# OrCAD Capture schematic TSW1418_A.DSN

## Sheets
1 BLOCK DIAGRAM: title: SCH, TSW1418EVM; rev: A; note: DC069
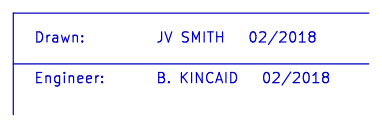
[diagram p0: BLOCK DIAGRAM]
2 LEDS, SWITCH & CLK SMAS: size B
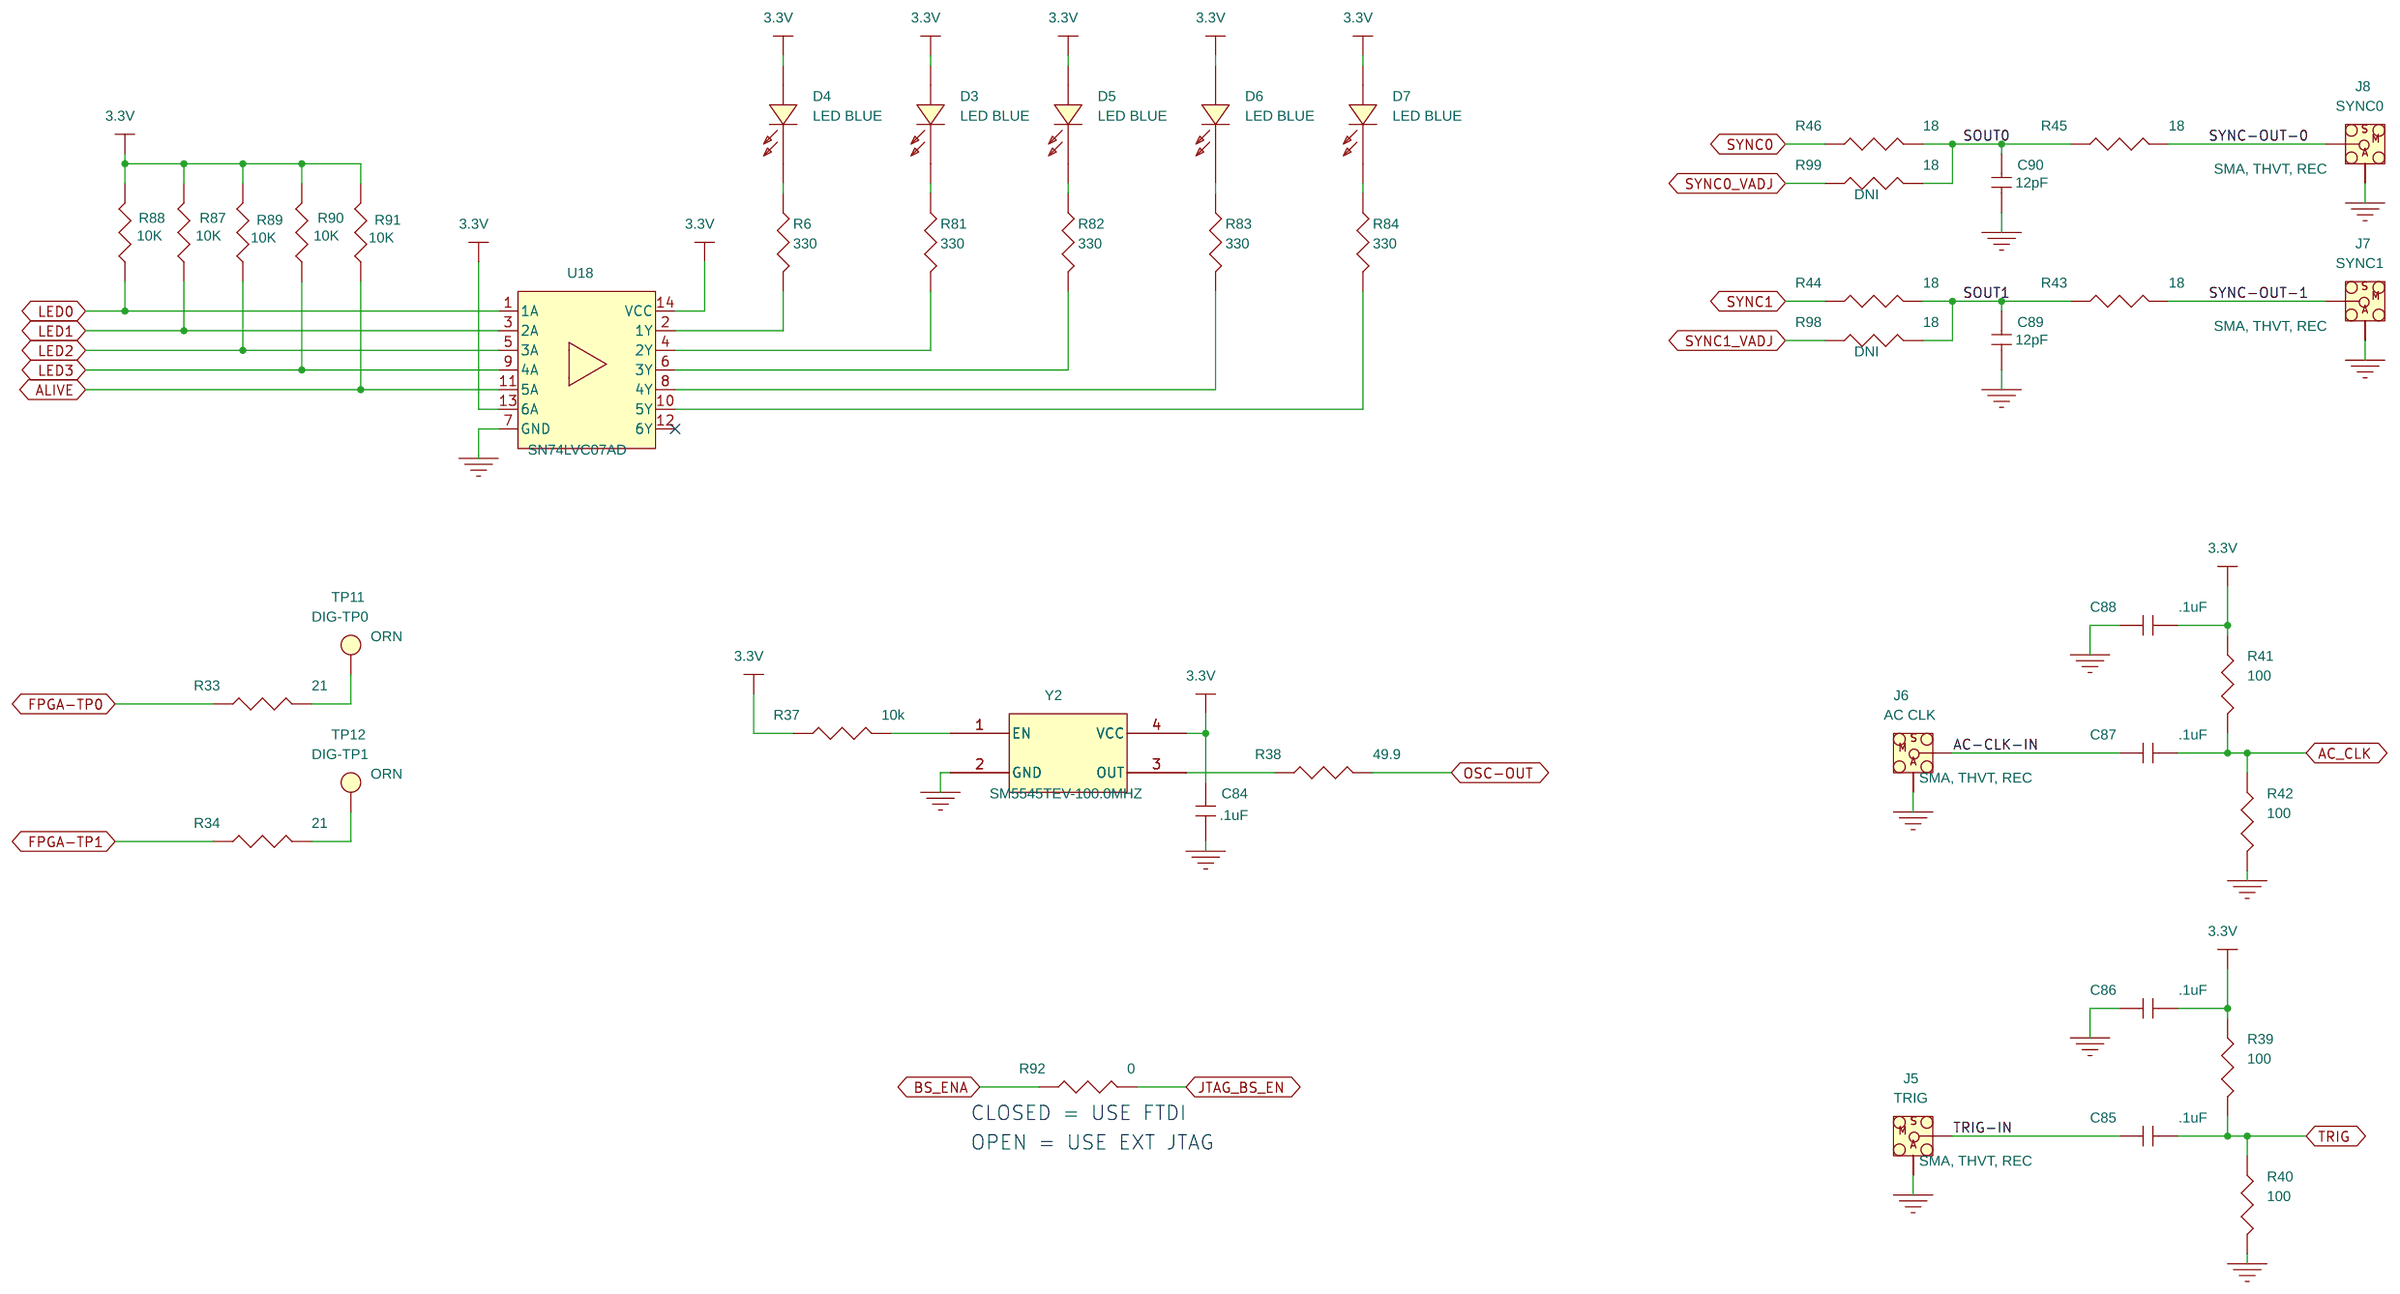
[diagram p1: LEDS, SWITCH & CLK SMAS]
3 ADC Interface, CMOS Header: size B
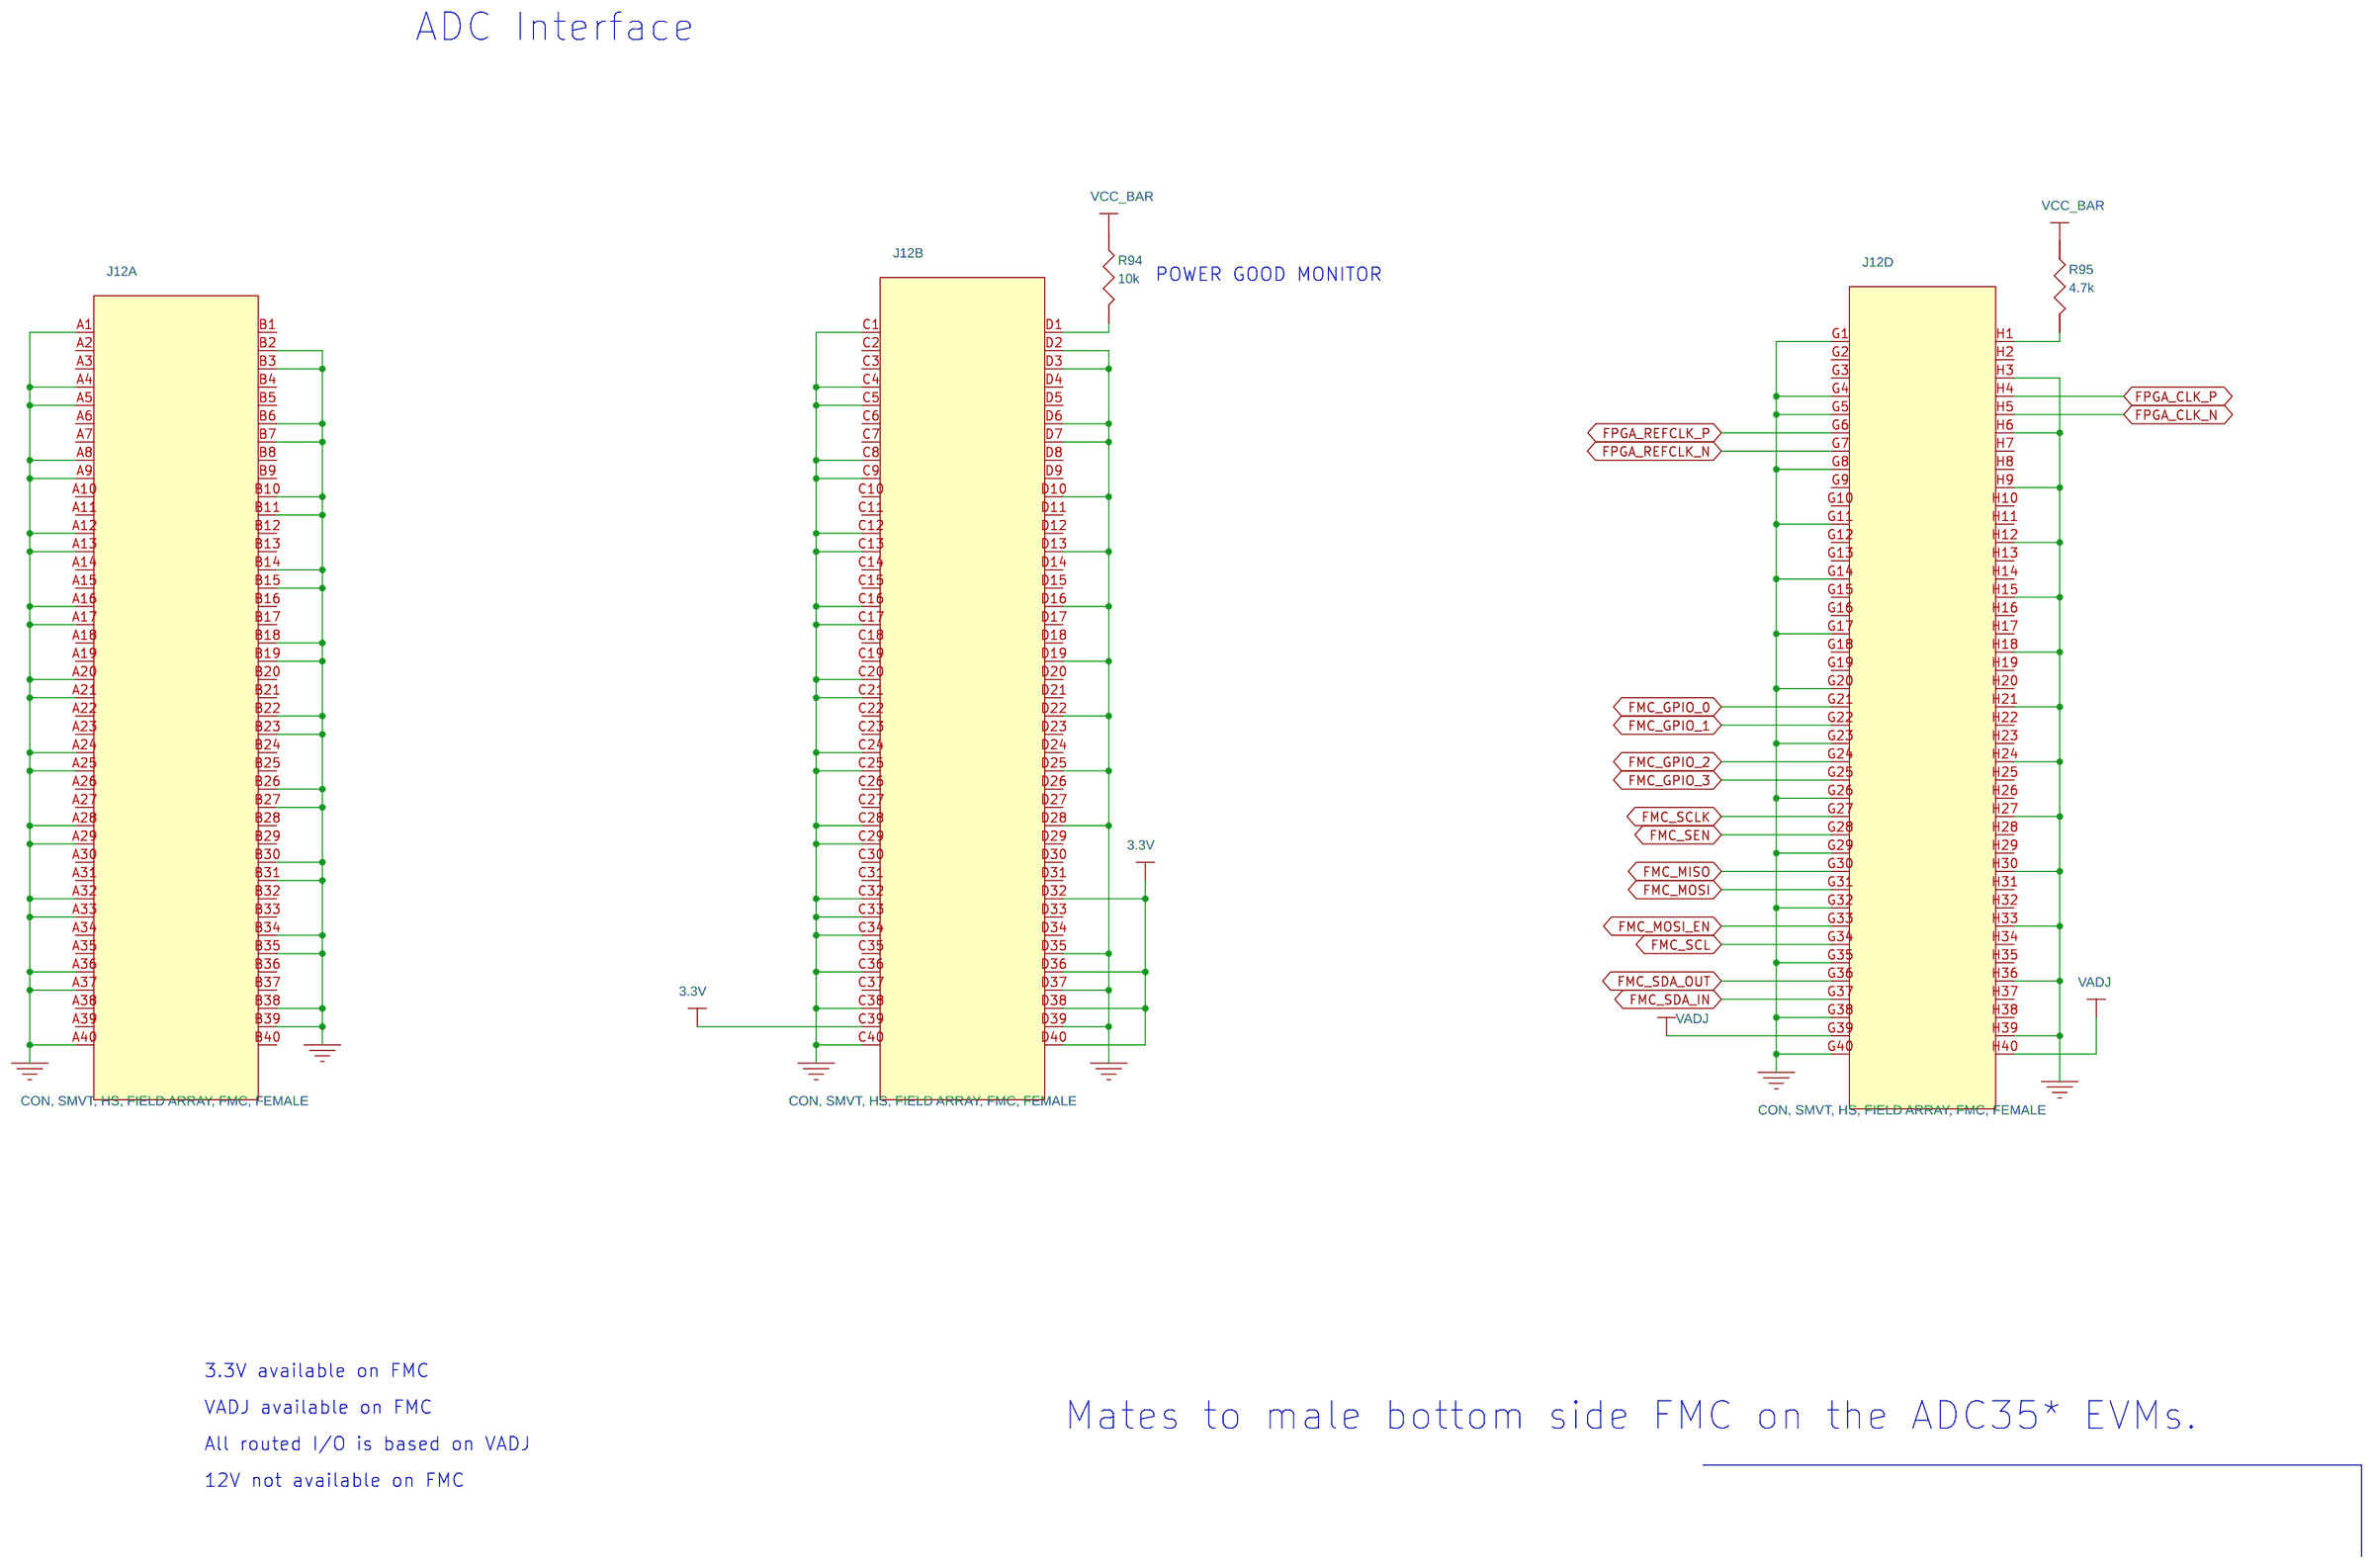
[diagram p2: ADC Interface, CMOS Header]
4 ADC I/F, FMC: size B
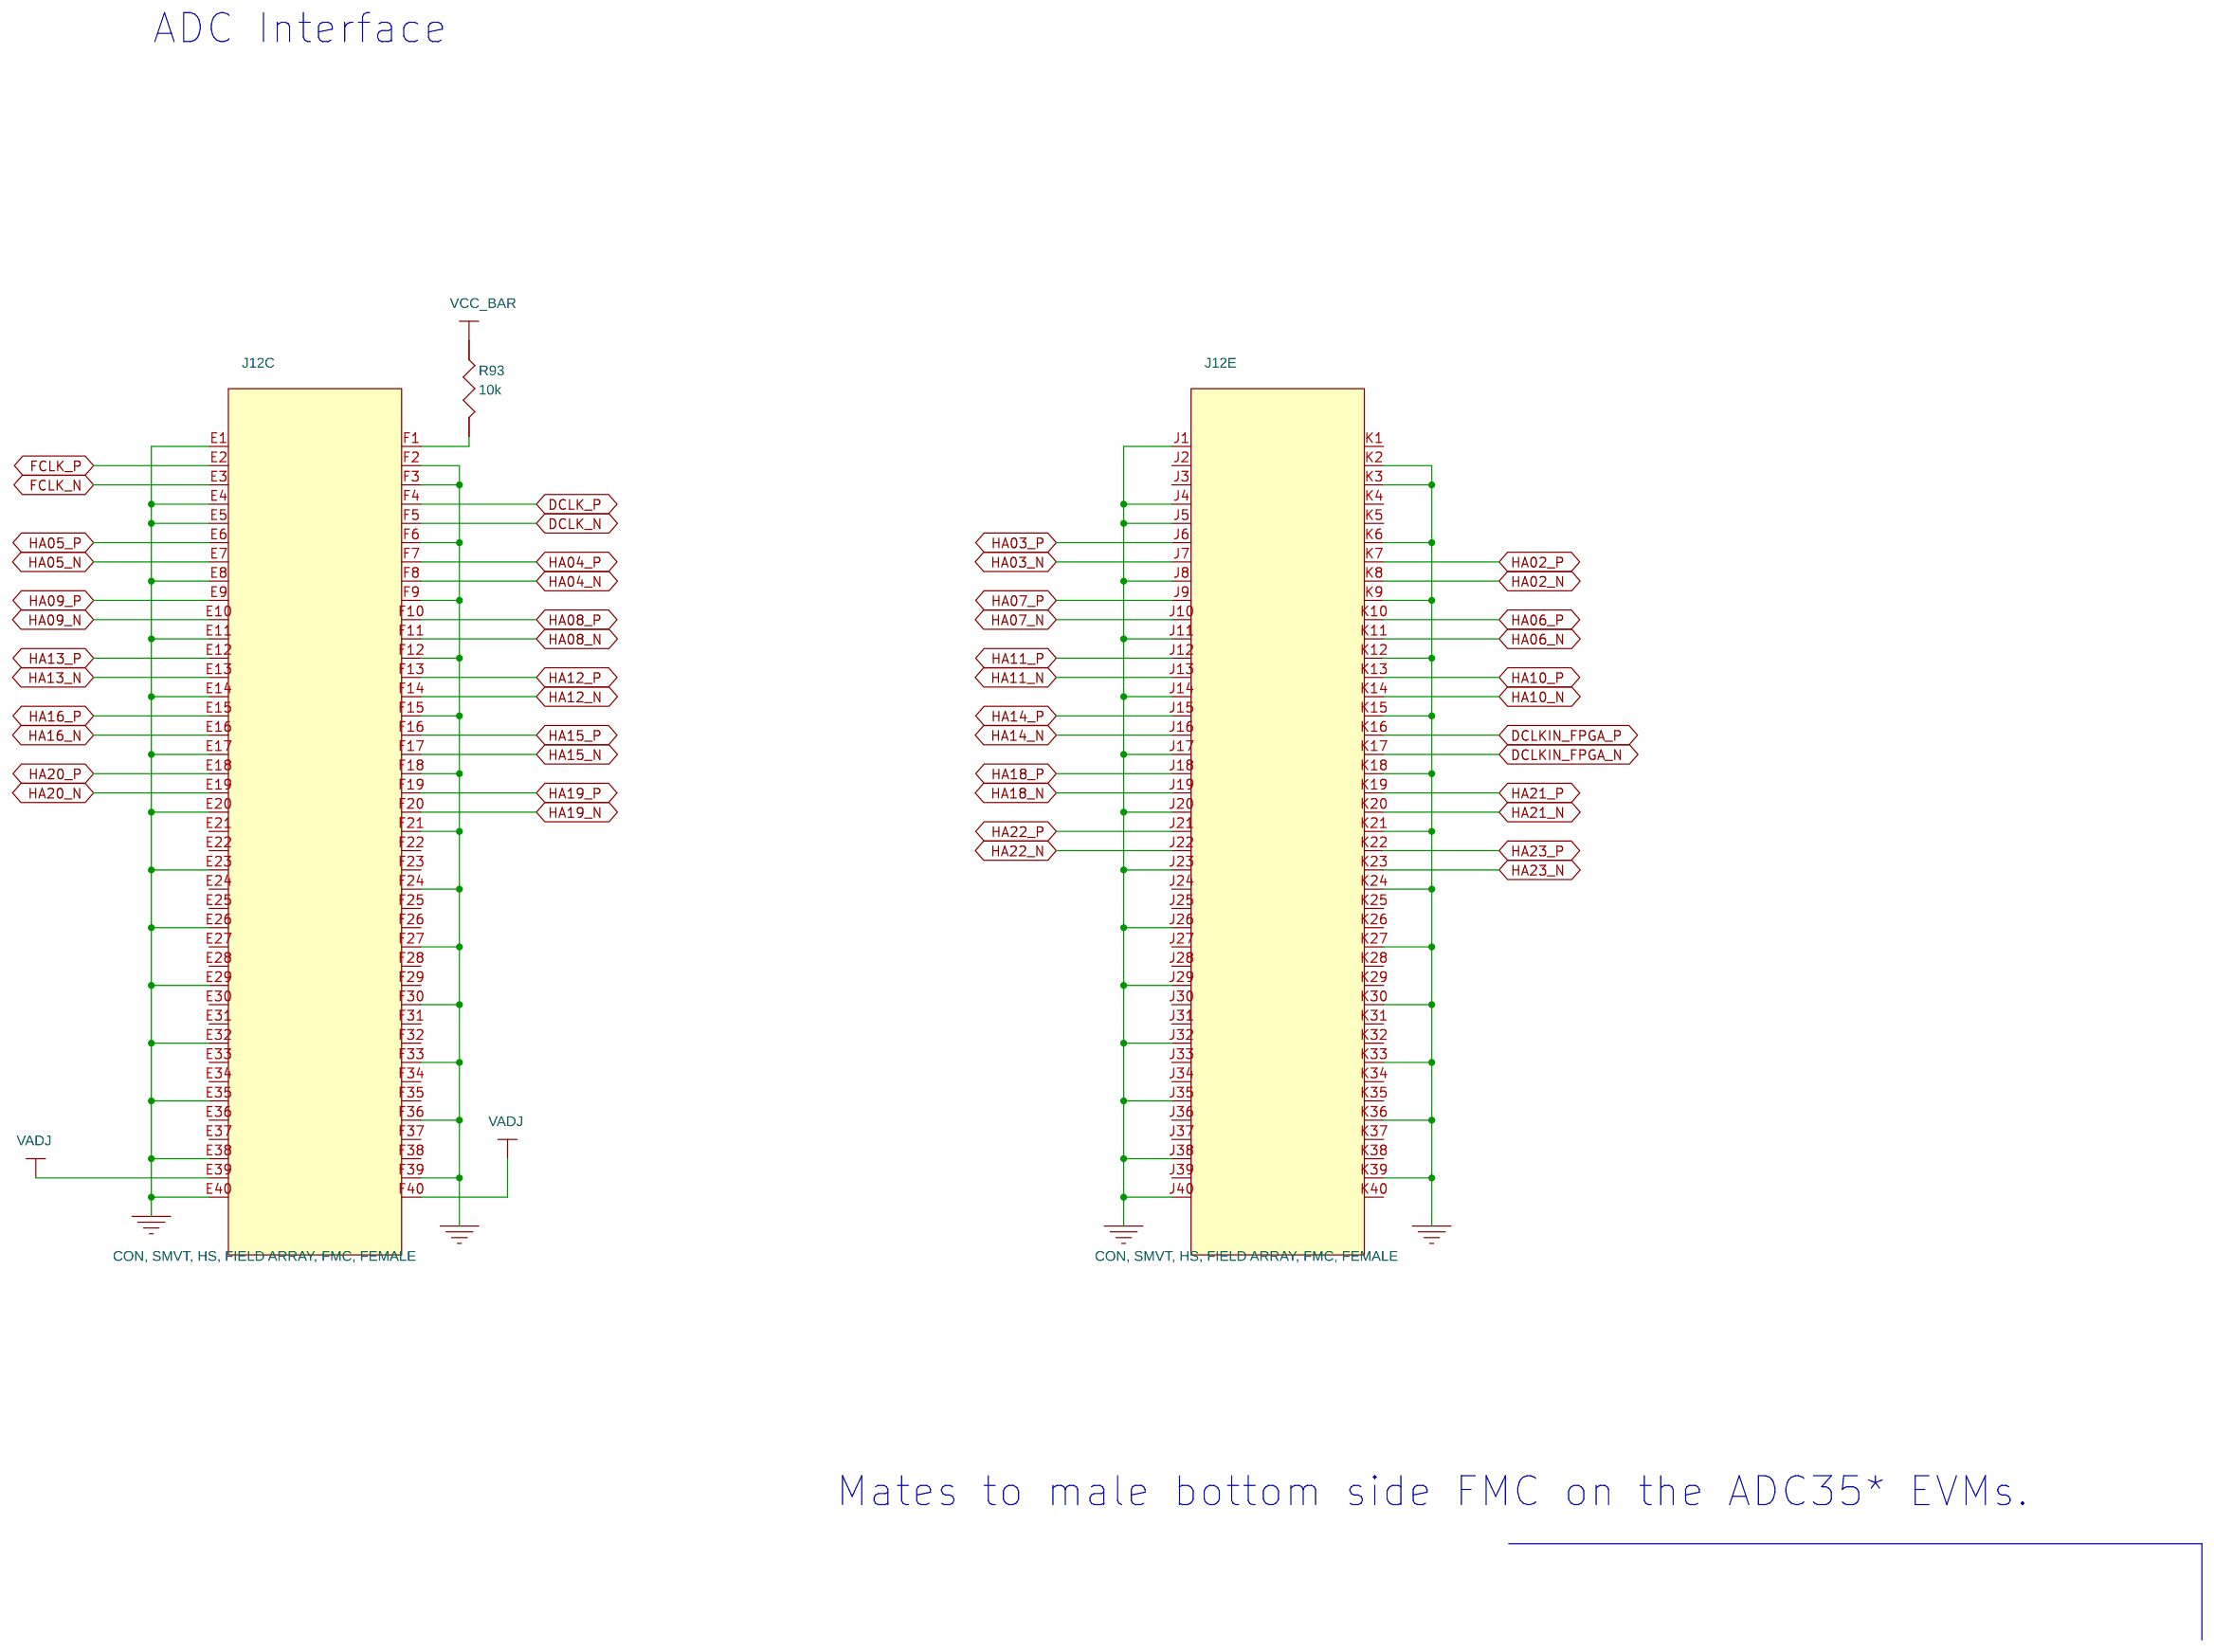
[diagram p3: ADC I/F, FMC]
5 USB: size B
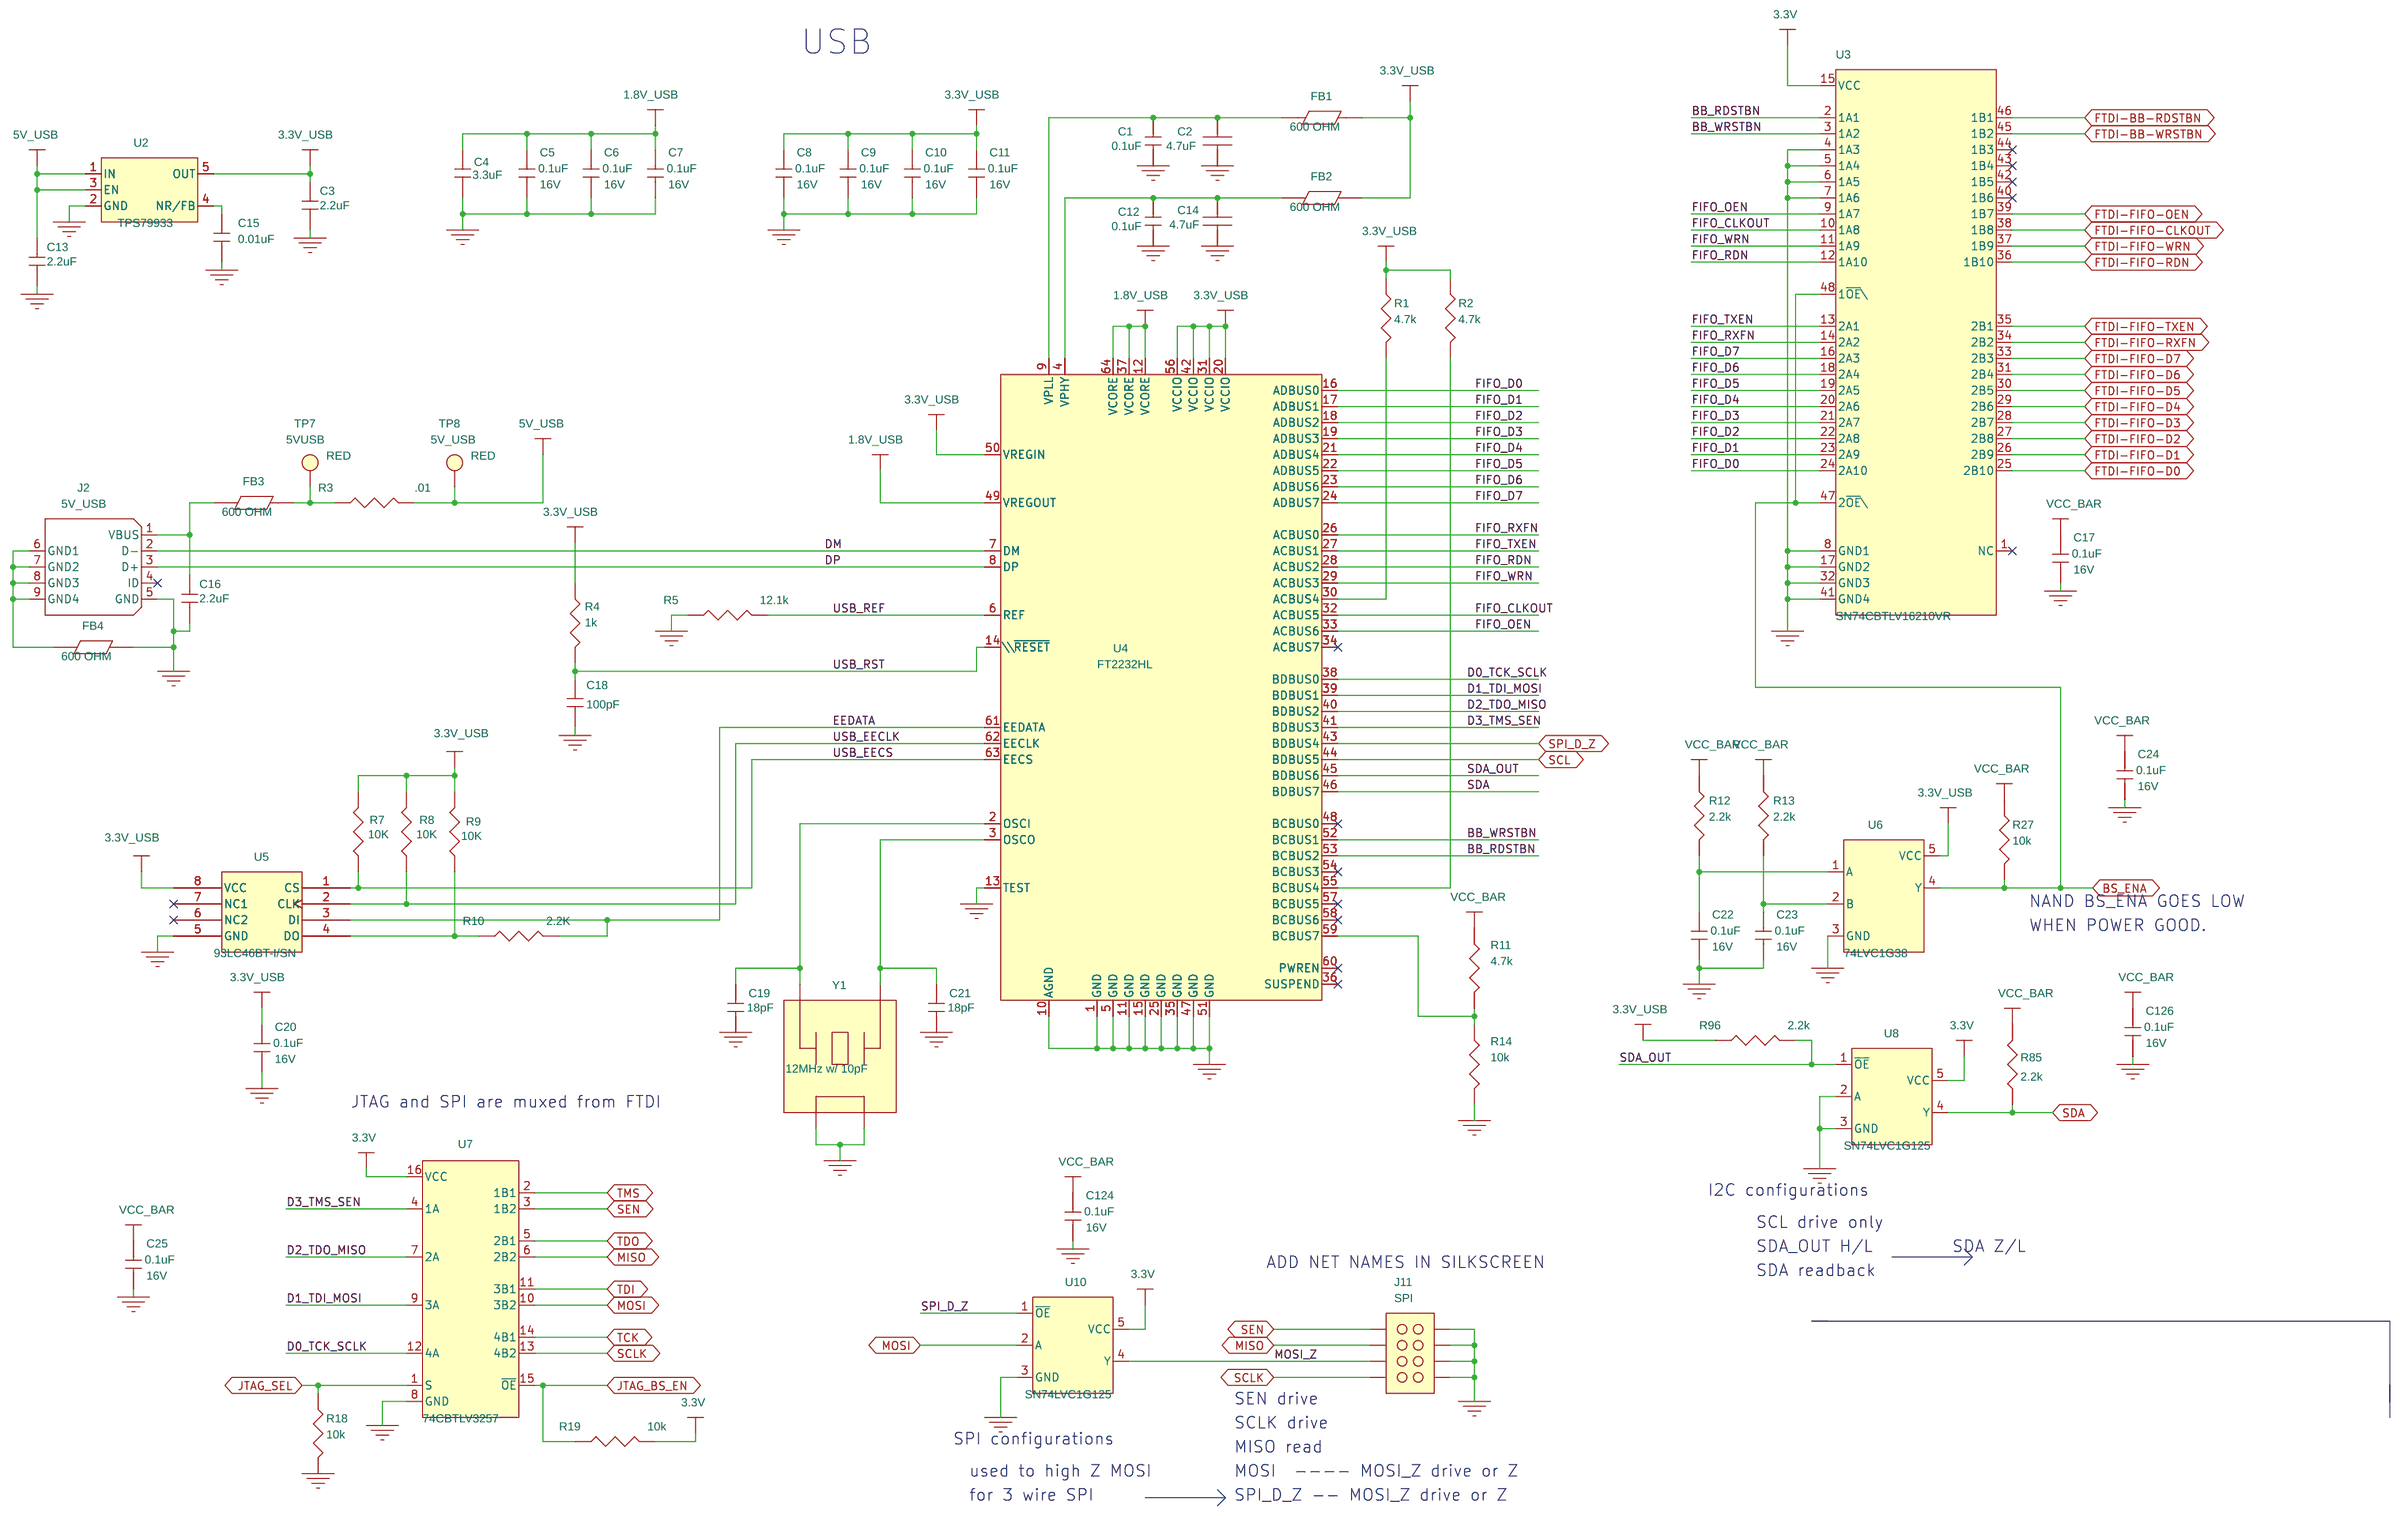
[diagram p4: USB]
6 FPGA Configuration: size B
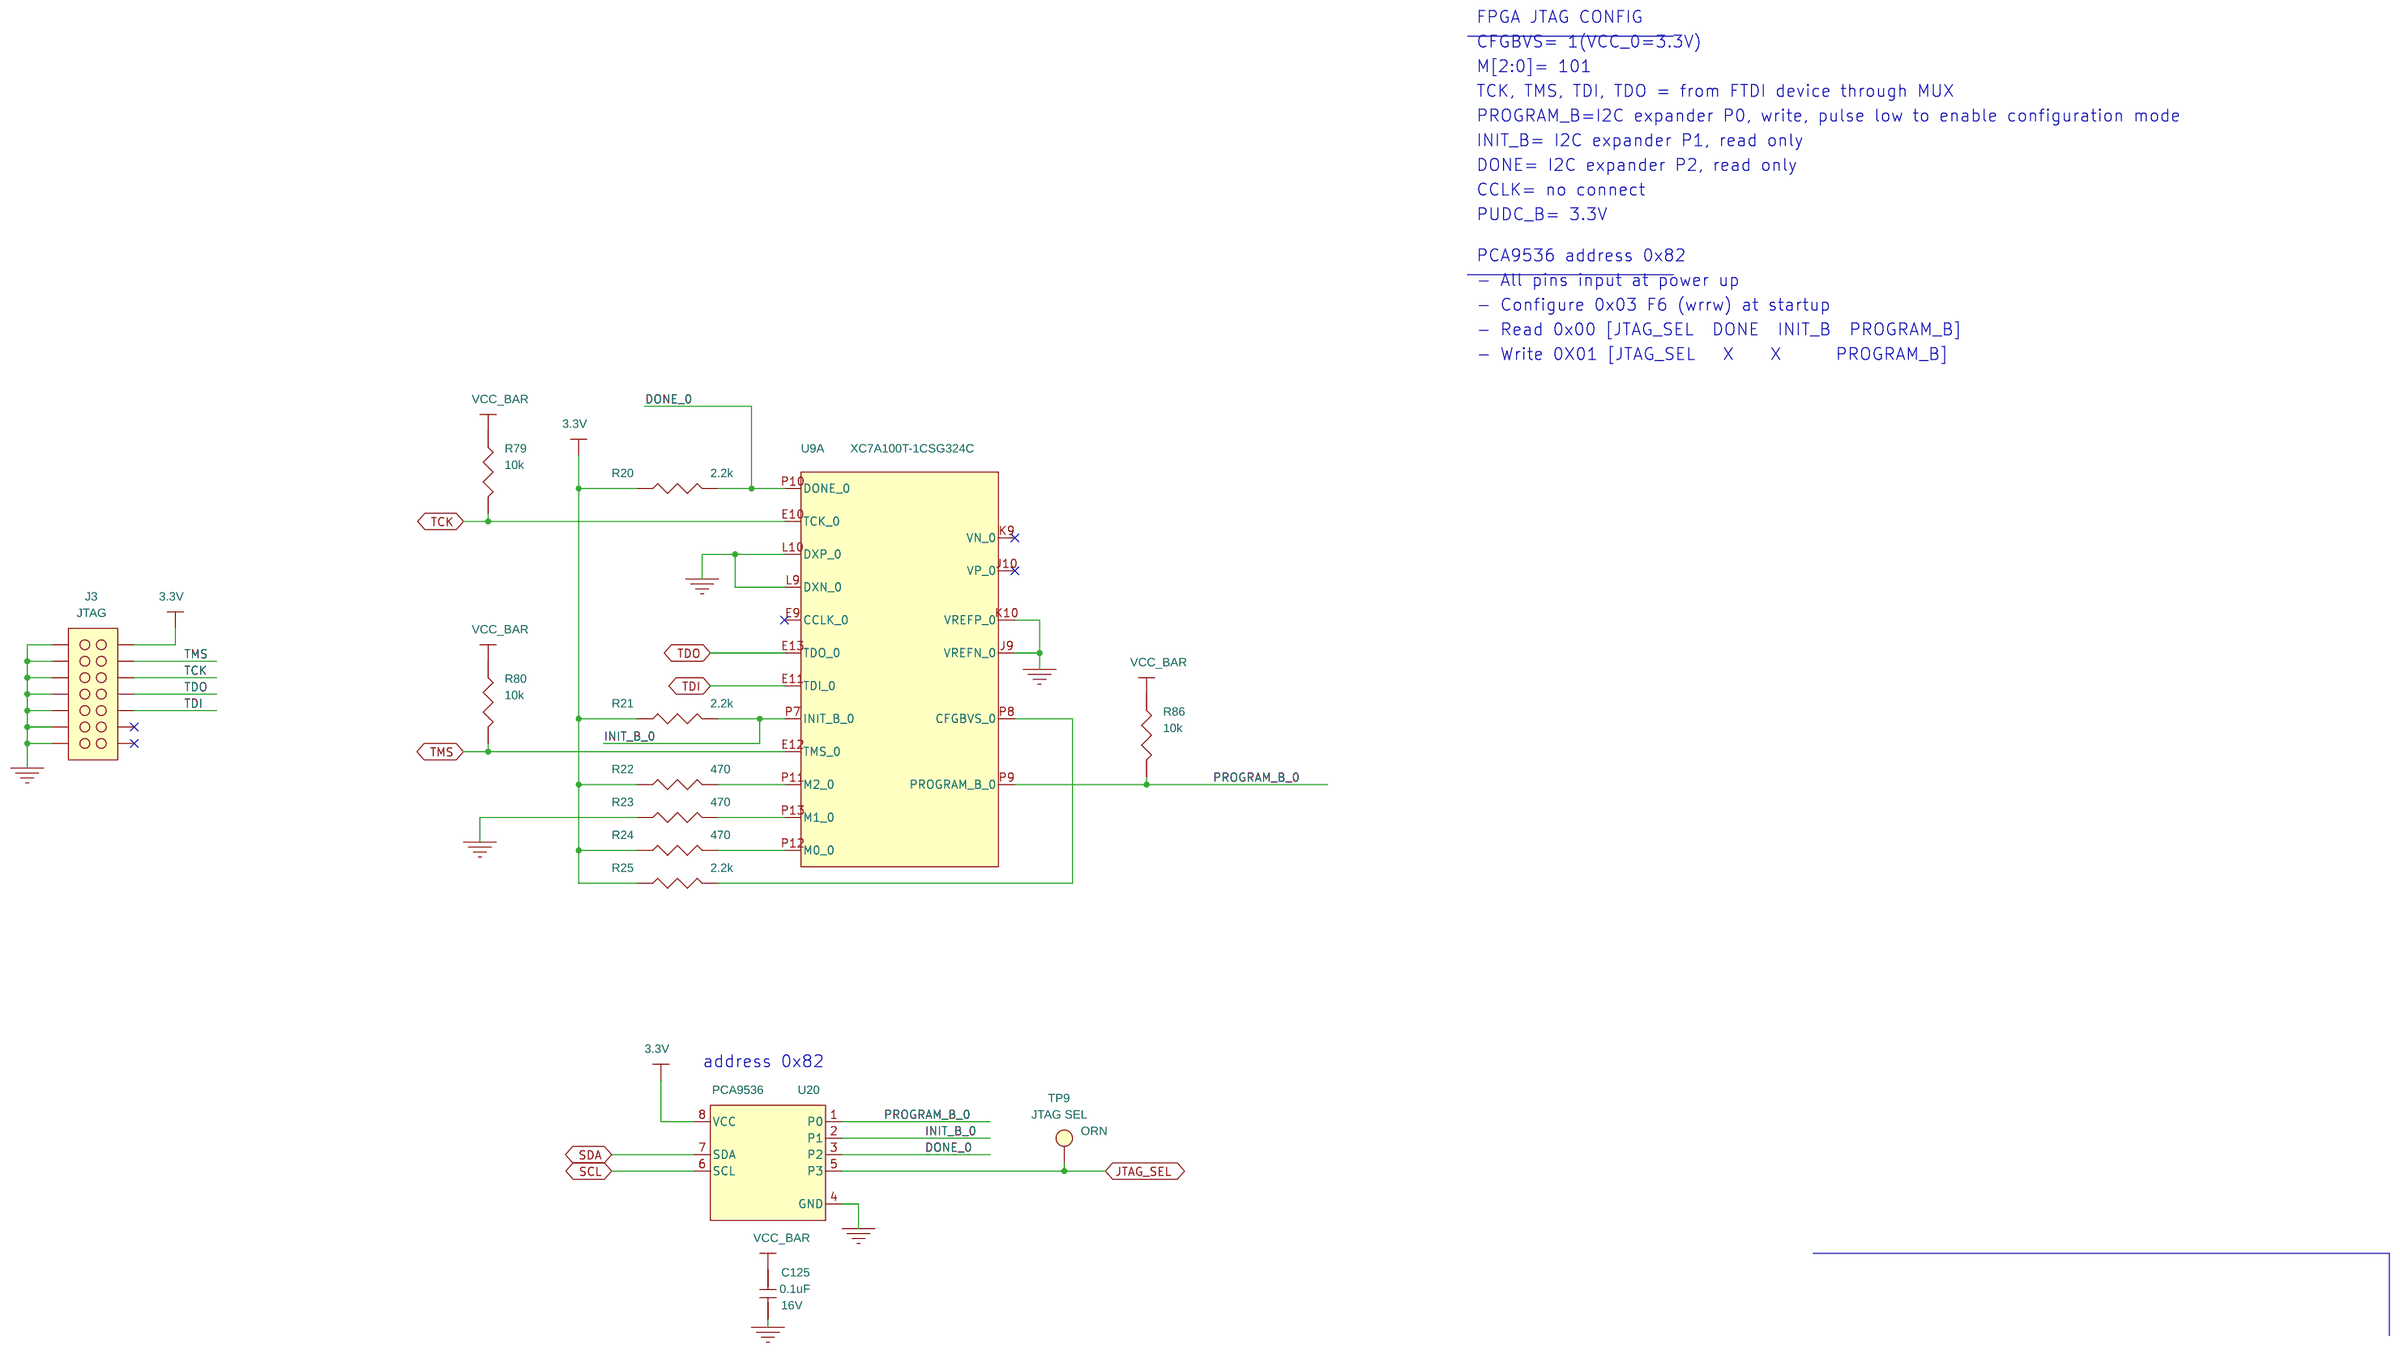
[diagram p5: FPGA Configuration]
7 Bank 14 & 15: size B
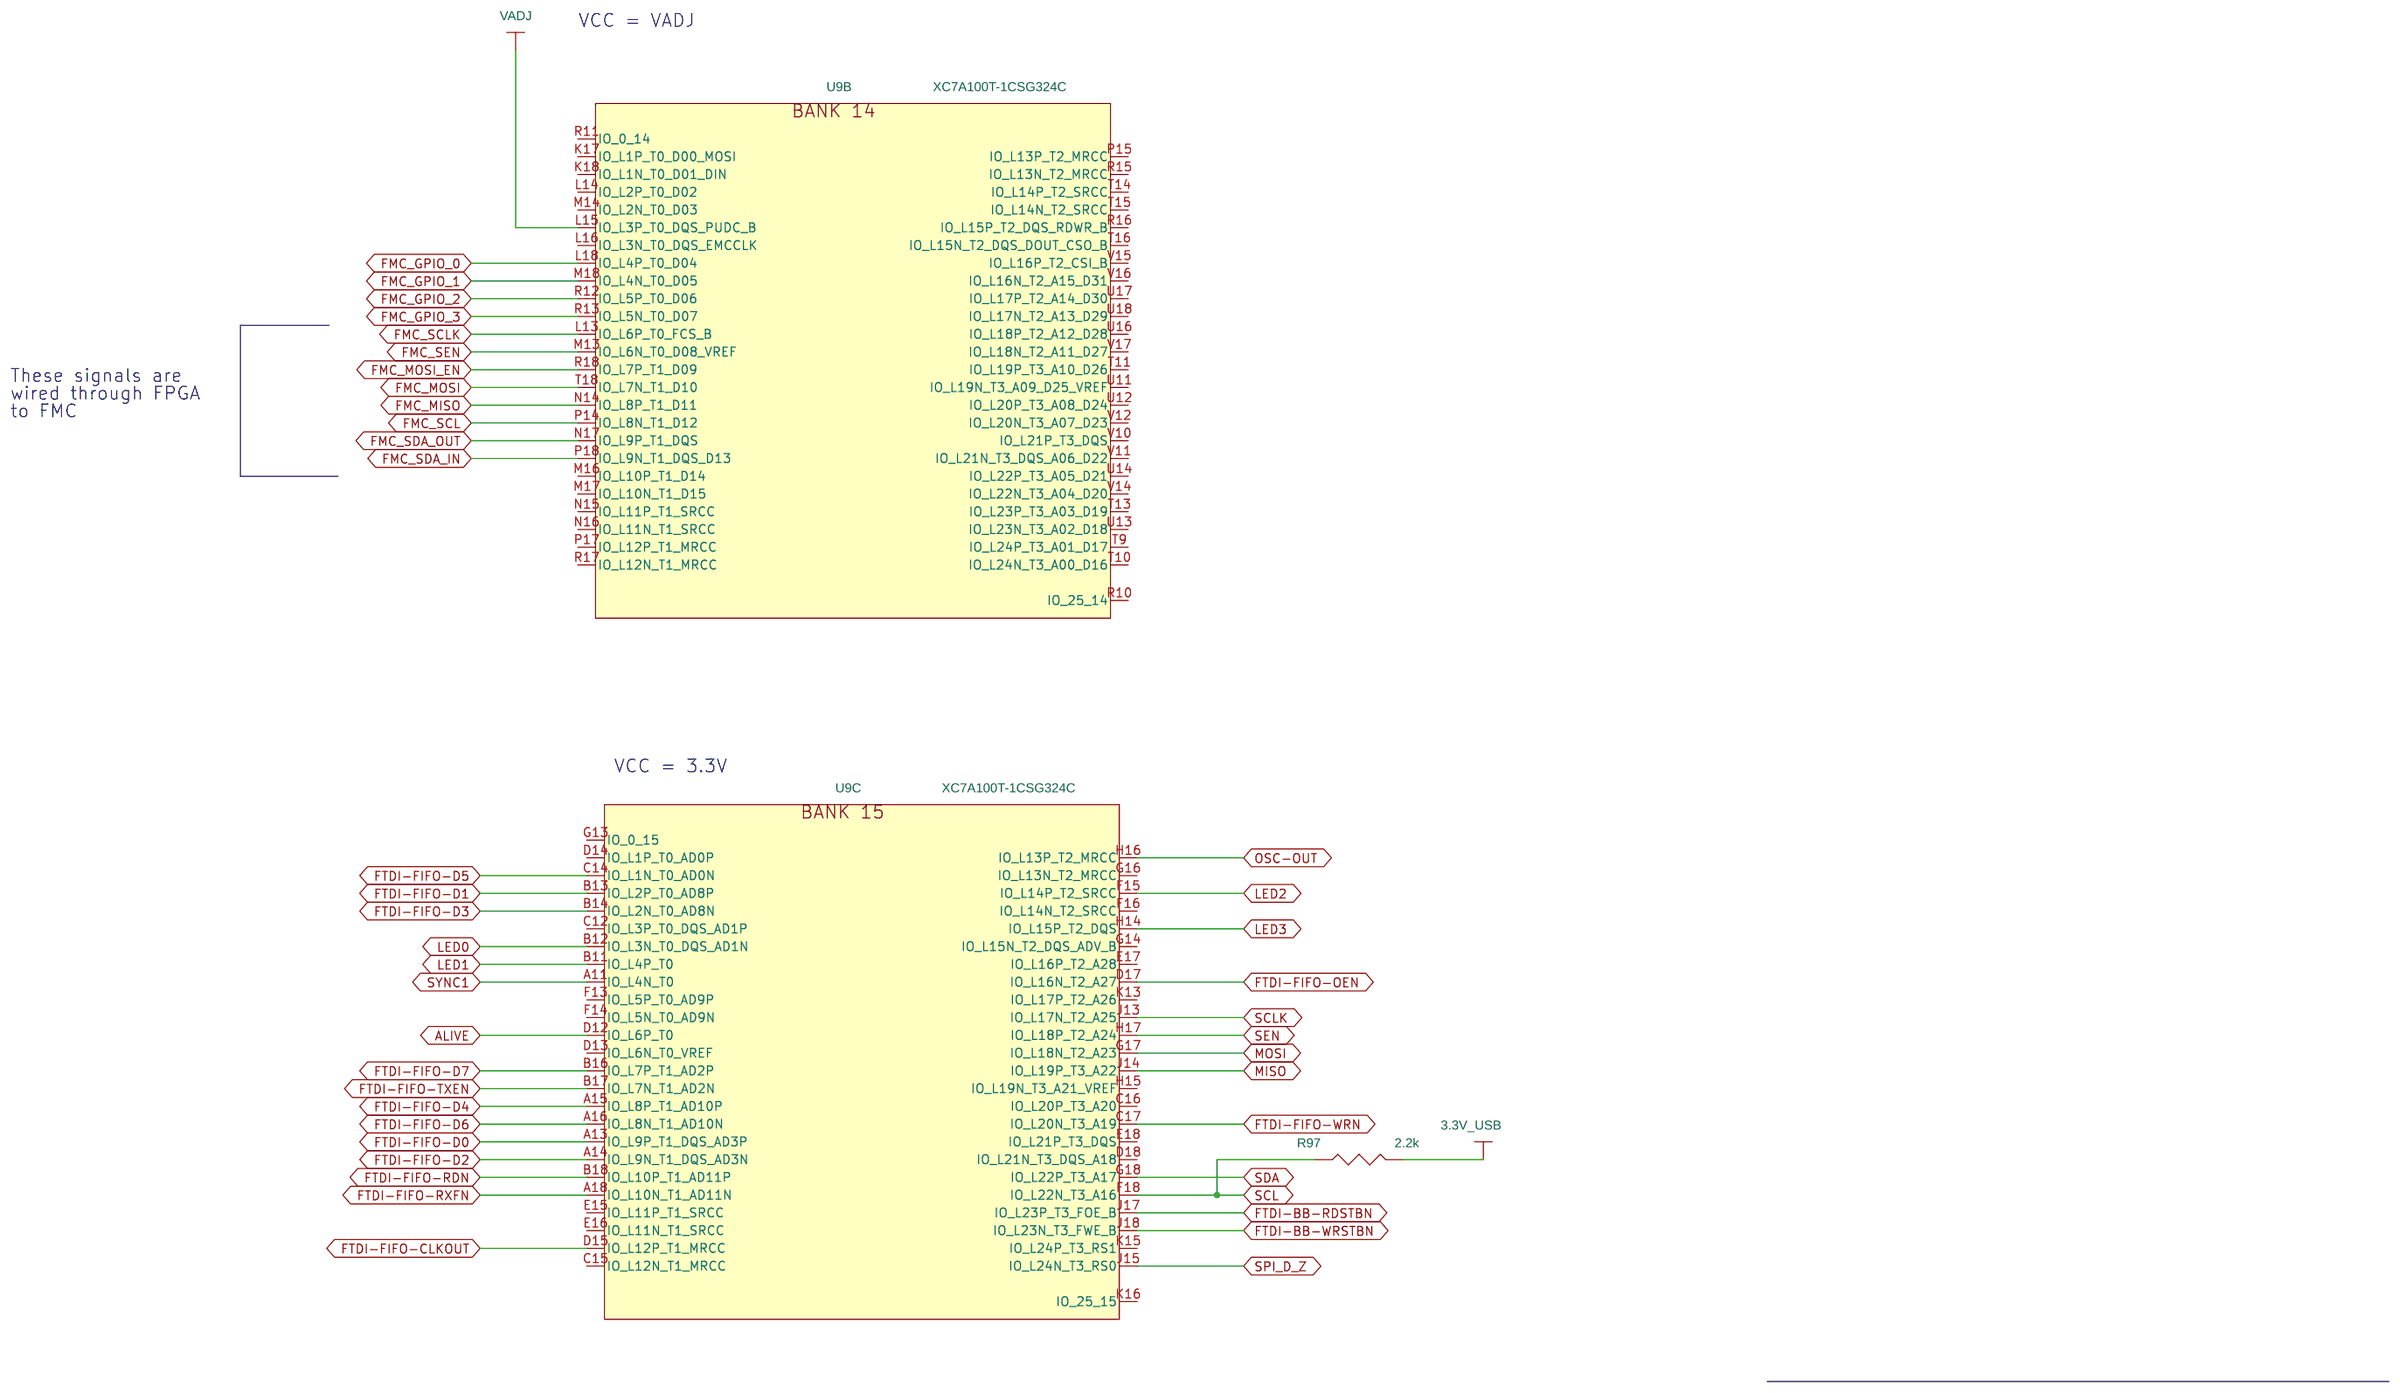
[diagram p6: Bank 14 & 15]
8 Bank 16 & 34 & 35: size B
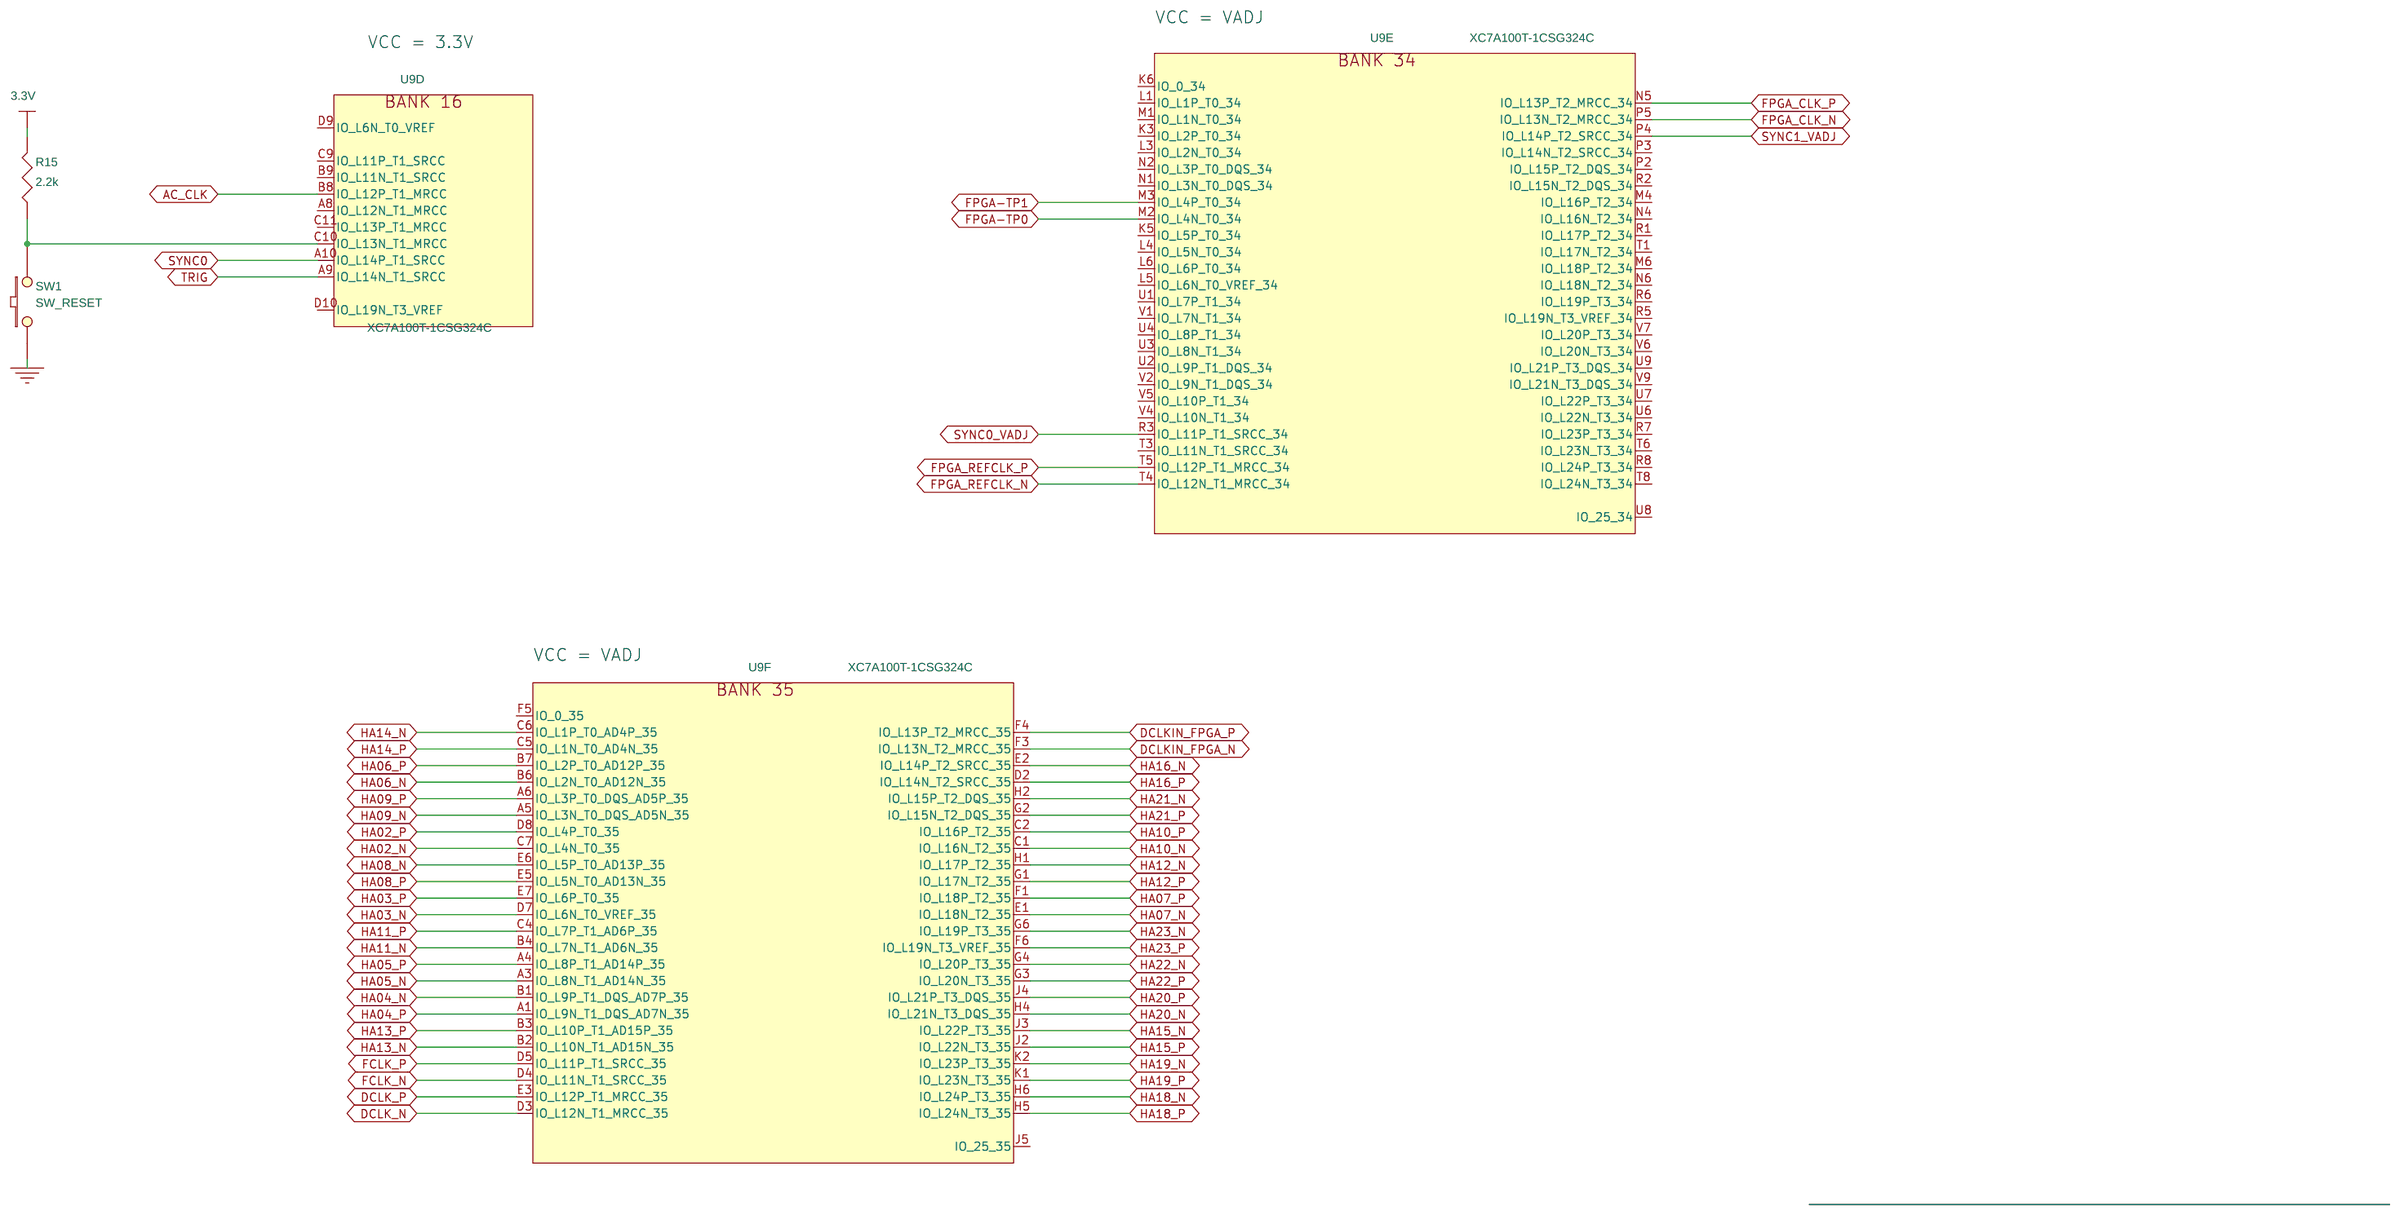
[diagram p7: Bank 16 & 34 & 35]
9 Main Power: size B
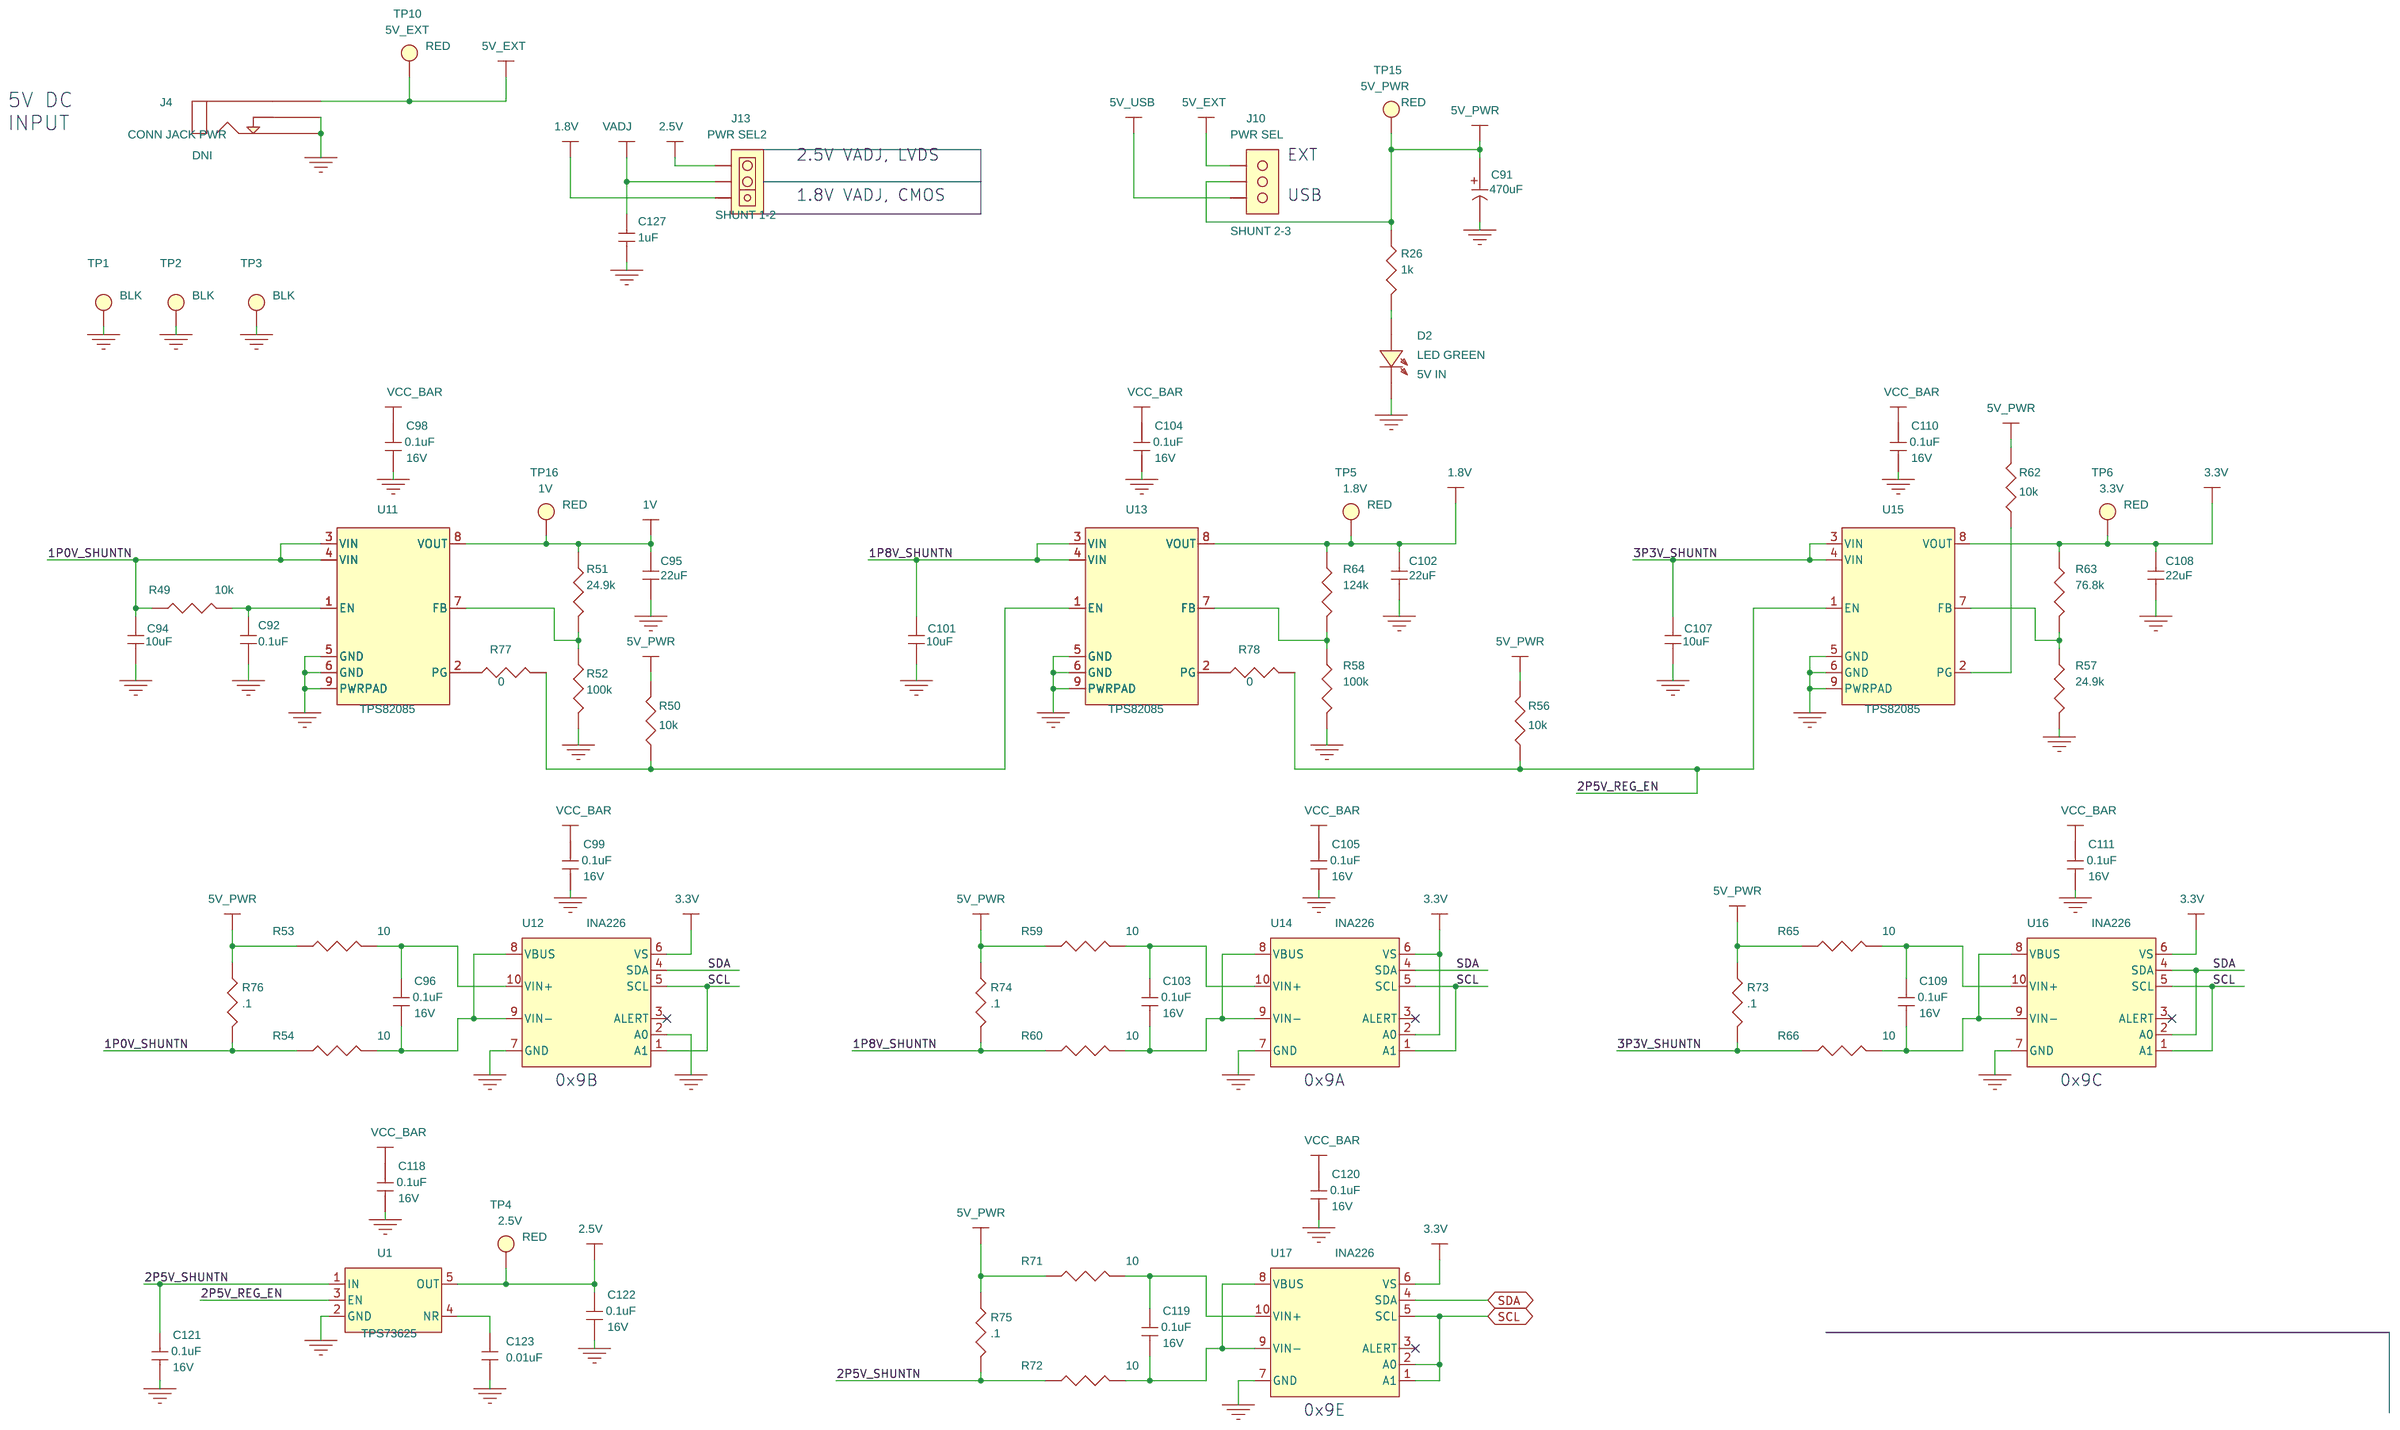
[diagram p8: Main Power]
10 FPGA Ground & Decoupling: size B
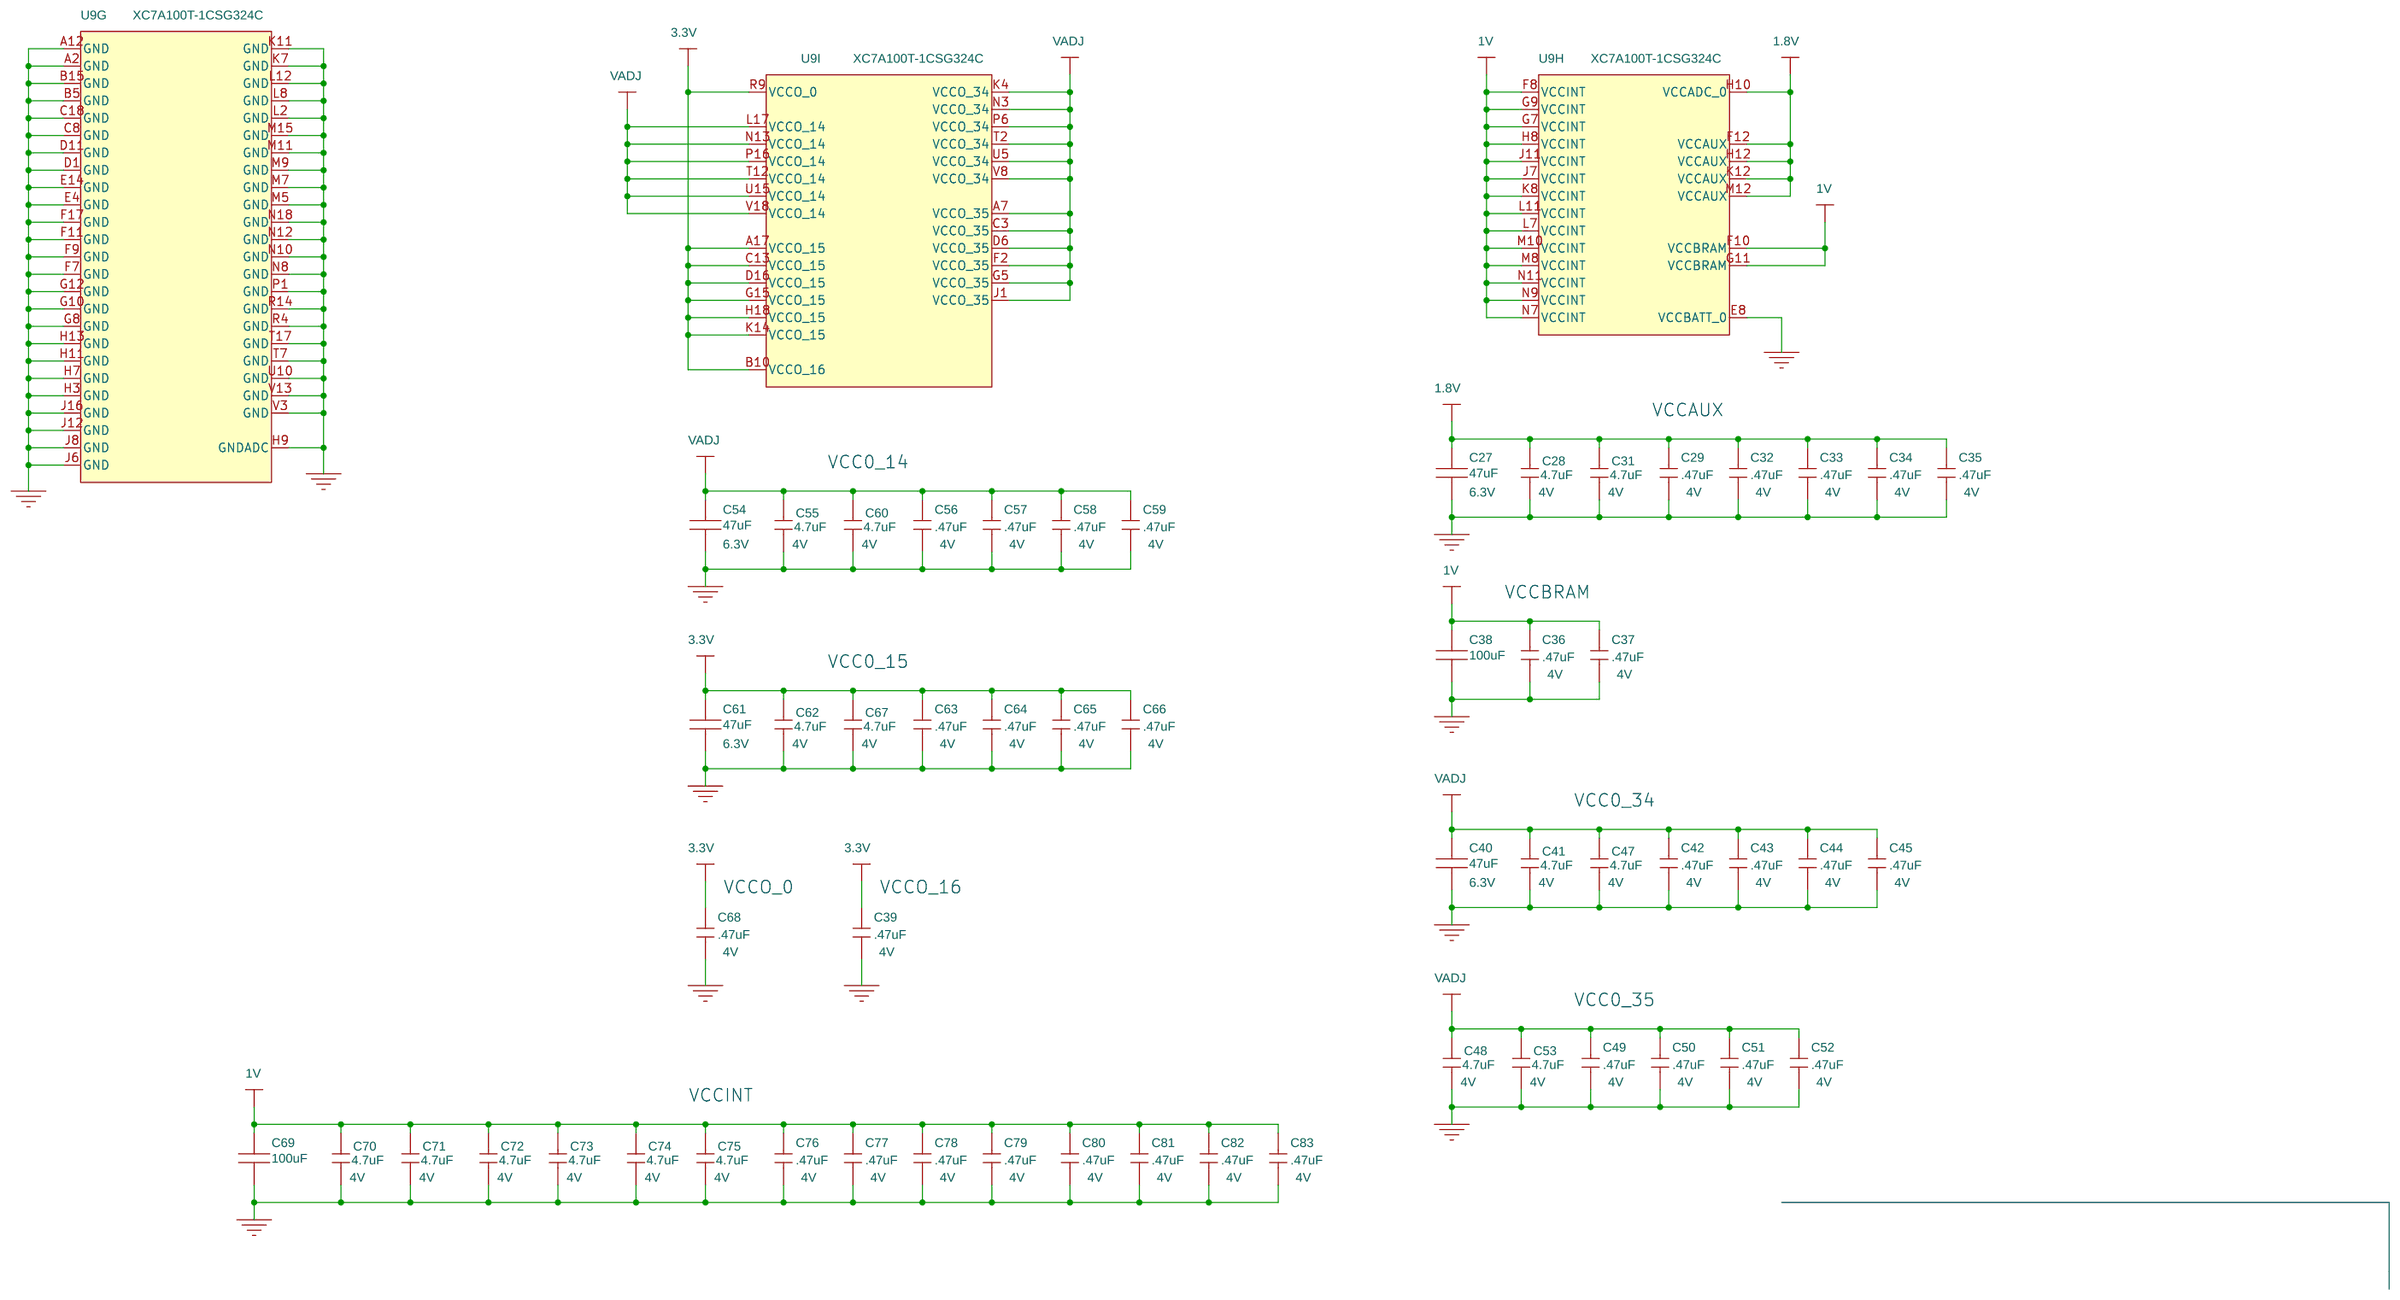
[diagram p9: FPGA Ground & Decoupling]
11 Mechanical: size B
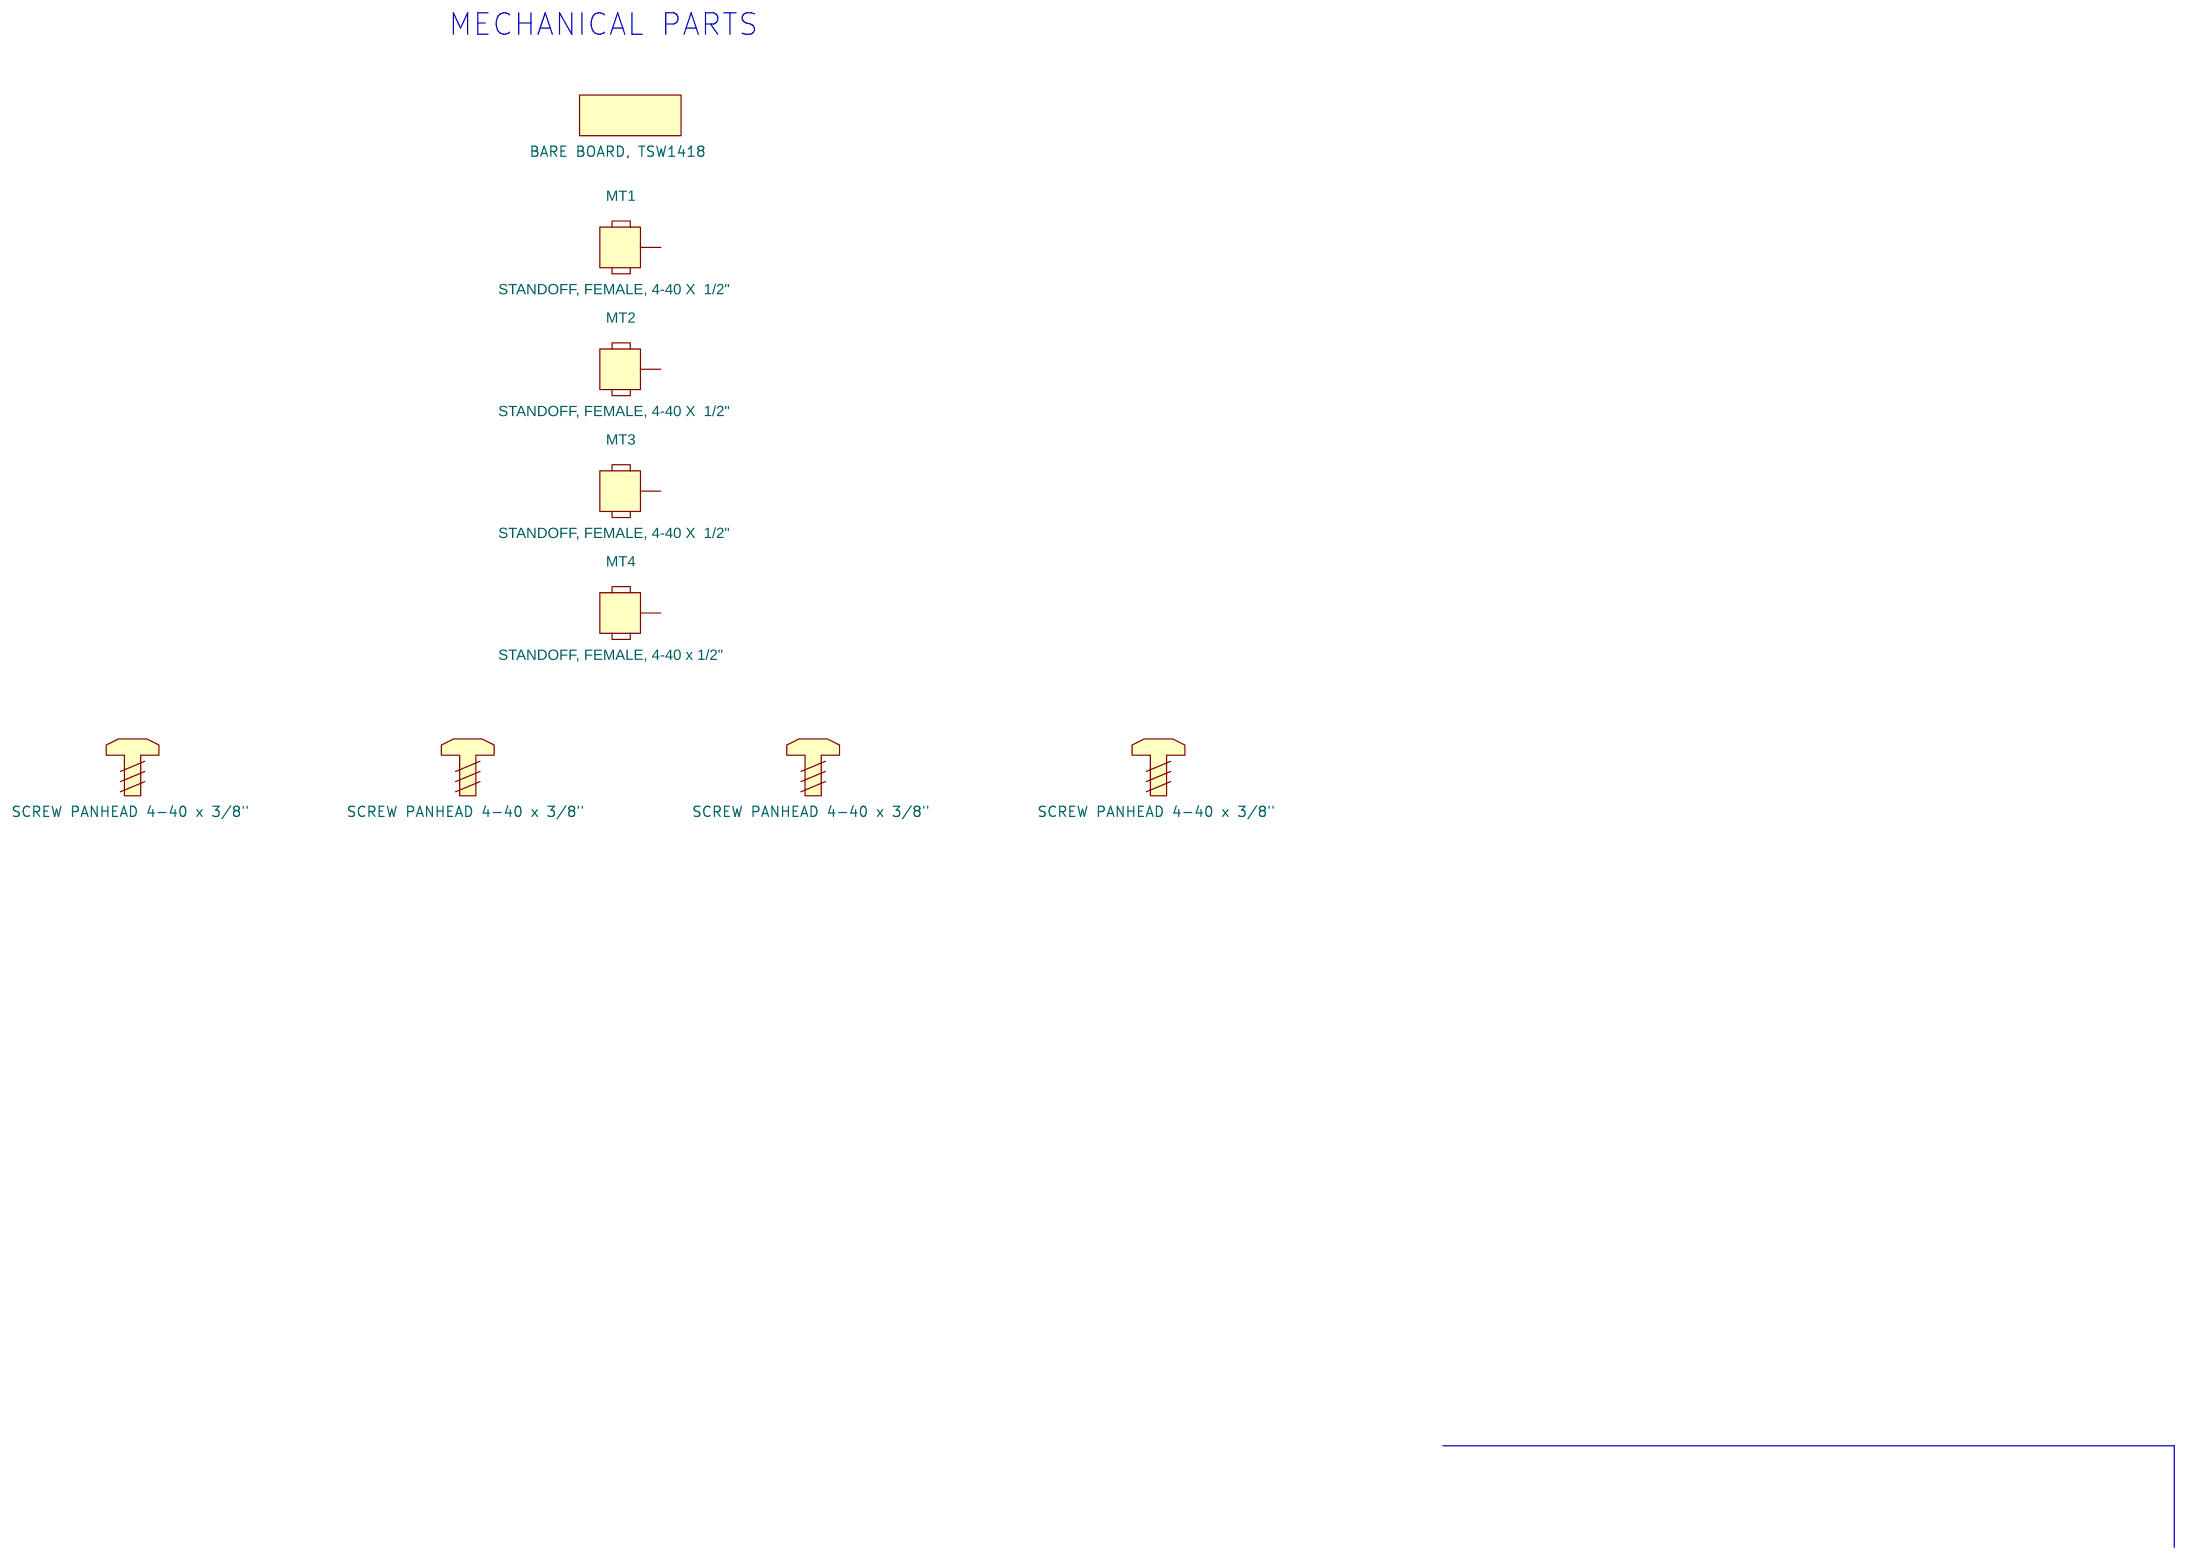
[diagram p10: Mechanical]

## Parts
sheet ADC I/F, FMC
R93  10k  [0402]
sheet ADC Interface, CMOS Header
J12  CON, SMVT, HS, FIELD ARRAY, FMC, FEMALE  [CON_SMVT_40X10_SEAF_MTG]  (sections A,B,C,D,E)
R94  10k  [0402]
R95  4.7k  [0402]
sheet Bank 14 & 15
R97  2.2k  [0402]
sheet Bank 16 & 34 & 35
R15  2.2k  [0402]
SW1  SW, PUSHBUTTON, SPST-NO  [SW_RESET_PTS635]
sheet FPGA Configuration
C125  0.1uF  [0603]
J3  CON, SMVT, 2X7, 2MM, MALE  [HDR_SMVT_2x7_79_M]
R20  2.2k  [0402]
R21  2.2k  [0402]
R22  470  [0402]
R23  470  [0402]
R24  470  [0402]
R25  2.2k  [0402]
R79  10k  [0402]
R80  10k  [0402]
R86  10k  [0402]
TP9  ORN  [TP_THVT_100_RND]
U20  PCA9536  [PSOP_8_118x118_26_DGK]
sheet FPGA Ground & Decoupling
C27  47uF  [1206]
C28  4.7uF  [0201]
C29  .47uF  [0201]
C31  4.7uF  [0201]
C32  .47uF  [0201]
C33  .47uF  [0201]
C34  .47uF  [0201]
C35  .47uF  [0201]
C36  .47uF  [0201]
C37  .47uF  [0201]
C38  100uF  [1210]
C39  .47uF  [0201]
C40  47uF  [1206]
C41  4.7uF  [0201]
C42  .47uF  [0201]
C43  .47uF  [0201]
C44  .47uF  [0201]
C45  .47uF  [0201]
C47  4.7uF  [0201]
C48  4.7uF  [0201]
C49  .47uF  [0201]
C50  .47uF  [0201]
C51  .47uF  [0201]
C52  .47uF  [0201]
C53  4.7uF  [0201]
C54  47uF  [1206]
C55  4.7uF  [0201]
C56  .47uF  [0201]
C57  .47uF  [0201]
C58  .47uF  [0201]
C59  .47uF  [0201]
C60  4.7uF  [0201]
C61  47uF  [1206]
C62  4.7uF  [0201]
C63  .47uF  [0201]
C64  .47uF  [0201]
C65  .47uF  [0201]
C66  .47uF  [0201]
C67  4.7uF  [0201]
C68  .47uF  [0201]
C69  100uF  [1210]
C70  4.7uF  [0201]
C71  4.7uF  [0201]
C72  4.7uF  [0201]
C73  4.7uF  [0201]
C74  4.7uF  [0201]
C75  4.7uF  [0201]
C76  .47uF  [0201]
C77  .47uF  [0201]
C78  .47uF  [0201]
C79  .47uF  [0201]
C80  .47uF  [0201]
C81  .47uF  [0201]
C82  .47uF  [0201]
C83  .47uF  [0201]
U9  XC7A100T-1CSG324C  [BGA_324_15MMx15MM_0p8MM]  (sections A,B,C,D,E,F,G,H,I)
sheet LEDS, SWITCH & CLK SMAS
C84  .1uF  [0402]
C85  .1uF  [0402]
C86  .1uF  [0402]
C87  .1uF  [0402]
C88  .1uF  [0402]
C89  12pF  [0402]
C90  12pF  [0402]
D3  LED BLUE  [LED_0603]
D4  LED BLUE  [LED_0603]
D5  LED BLUE  [LED_0603]
D6  LED BLUE  [LED_0603]
D7  LED BLUE  [LED_0603]
J5  SMA, THVT, REC  [SMA_THVT_312x312]
J6  SMA, THVT, REC  [SMA_THVT_312x312]
J7  SMA, THVT, REC  [SMA_THVT_312x312]
J8  SMA, THVT, REC  [SMA_THVT_312x312]
R6  330  [0402]
R33  21  [0402]
R34  21  [0402]
R37  10k  [0402]
R38  49.9  [0402]
R39  100  [0402]
R40  100  [0402]
R41  100  [0402]
R42  100  [0402]
R43  18  [0402]
R44  18  [0402]
R45  18  [0402]
R46  18  [0402]
R81  330  [0402]
R82  330  [0402]
R83  330  [0402]
R84  330  [0402]
R87  10K  [0402]
R88  10K  [0402]
R89  10K  [0402]
R90  10K  [0402]
R91  10K  [0402]
R92  0  [0805]
R98  18  [0402]
R99  18  [0402]
TP11  ORN  [TP_THVT_100_RND]
TP12  ORN  [TP_THVT_100_RND]
U18  SN74LVC07AD  [SOIC_14_344x157_50]
Y2  SM5545TEV-100.0MHZ  [OSC-3X5mm]
sheet Main Power
C91  470uF  [TANT_B]
C92  0.1uF  [0603]
C94  10uF  [0603]
C95  22uF  [0603]
C96  0.1uF  [0603]
C98  0.1uF  [0603]
C99  0.1uF  [0603]
C101  10uF  [0603]
C102  22uF  [0603]
C103  0.1uF  [0603]
C104  0.1uF  [0603]
C105  0.1uF  [0603]
C107  10uF  [0603]
C108  22uF  [0603]
C109  0.1uF  [0603]
C110  0.1uF  [0603]
C111  0.1uF  [0603]
C118  0.1uF  [0603]
C119  0.1uF  [0603]
C120  0.1uF  [0603]
C121  0.1uF  [0603]
C122  0.1uF  [0603]
C123  0.01uF  [0603]
C127  1uF  [0805]
D2  LED GREEN  [LED_1206]
J4  CONN JACK PWR  [CON_RAPC722_JACK_THVT_3]
J10  HDR, THVT, 3POS, .100  [HDR_THVT_1x3_100_M]
J13  HDR, THVT, 3POS, .100  [HDR_THVT_1x3_100_M]
R26  1k  [0402]
R49  10k  [0603]
R50  10k  [0603]
R51  24.9k  [0603]
R52  100k  [0603]
R53  10  [0603]
R54  10  [0603]
R56  10k  [0603]
R57  24.9k  [0603]
R58  100k  [0603]
R59  10  [0603]
R60  10  [0603]
R62  10k  [0603]
R63  76.8k  [0603]
R64  124k  [0603]
R65  10  [0603]
R66  10  [0603]
R71  10  [0603]
R72  10  [0603]
R73  .1  [1210]
R74  .1  [1210]
R75  .1  [1210]
R76  .1  [1210]
R77  0  [0603]
R78  0  [0603]
TP1  BLK  [TP_THVT_100_RND_GND]
TP2  BLK  [TP_THVT_100_RND_GND]
TP3  BLK  [TP_THVT_100_RND_GND]
TP4  RED  [TP_THVT_100_RND]
TP5  RED  [TP_THVT_100_RND]
TP6  RED  [TP_THVT_100_RND]
TP10  RED  [TP_THVT_100_RND]
TP15  RED  [TP_THVT_100_RND]
TP16  RED  [TP_THVT_100_RND]
U1  TPS73625  [SOT-23_5_63x114_DBV]
U11  TPS82085  [uSIL_8_3MMx2p8MM_0p65MM]
U12  INA226  [PSOP_10_122x122_0p5mm_DGS]
U13  TPS82085  [uSIL_8_3MMx2p8MM_0p65MM]
U14  INA226  [PSOP_10_122x122_0p5mm_DGS]
U15  TPS82085  [uSIL_8_3MMx2p8MM_0p65MM]
U16  INA226  [PSOP_10_122x122_0p5mm_DGS]
U17  INA226  [PSOP_10_122x122_0p5mm_DGS]
Z_SH-H1  SHUNT-HEADER
Z_SH-H2  SHUNT-HEADER
sheet Mechanical
MT1  STANDOFF, FEMALE, 4-40 X  1/2"  [MFG125_PLATED]
MT2  STANDOFF, FEMALE, 4-40 X  1/2"  [MFG125_PLATED]
MT3  STANDOFF, FEMALE, 4-40 X  1/2"  [MFG125_PLATED]
MT4  STANDOFF, FEMALE, 4-40 x 1/2"  [MFG125_PLATED]
Z_BOARD1  BARE BOARD, TSW1418
Z_SCREW1  SCREW PANHEAD 4-40 x 3/8"
Z_SCREW2  SCREW PANHEAD 4-40 x 3/8"
Z_SCREW3  SCREW PANHEAD 4-40 x 3/8"
Z_SCREW4  SCREW PANHEAD 4-40 x 3/8"
sheet USB
C1  0.1uF  [0603]
C2  4.7uF  [0603]
C3  2.2uF  [0603]
C4  3.3uF  [0603]
C5  0.1uF  [0603]
C6  0.1uF  [0603]
C7  0.1uF  [0603]
C8  0.1uF  [0603]
C9  0.1uF  [0603]
C10  0.1uF  [0603]
C11  0.1uF  [0603]
C12  0.1uF  [0603]
C13  2.2uF  [0603]
C14  4.7uF  [0603]
C15  0.01uF  [0603]
C16  2.2uF  [0402]
C17  0.1uF  [0603]
C18  100pF  [0402]
C19  18pF  [0402]
C20  0.1uF  [0603]
C21  18pF  [0402]
C22  0.1uF  [0603]
C23  0.1uF  [0603]
C24  0.1uF  [0603]
C25  0.1uF  [0603]
C124  0.1uF  [0603]
C126  0.1uF  [0603]
FB1  600 OHM  [IND_0603]
FB2  600 OHM  [IND_0603]
FB3  600 OHM  [IND_0603]
FB4  600 OHM  [IND_0603]
J2  CONN, USB, MINI  [CON_SMRT_USBMNE20_F]
J11  HDR, THVT, 8POS, .100  [HDR_THVT_2x4_100_M]
R1  4.7k  [0402]
R2  4.7k  [0402]
R3  .01  [0603]
R4  1k  [0402]
R5  12.1k  [0402]
R7  10K  [0402]
R8  10K  [0402]
R9  10K  [0402]
R10  2.2K  [0402]
R11  4.7k  [0402]
R12  2.2k  [0402]
R13  2.2k  [0402]
R14  10k  [0402]
R18  10k  [0402]
R19  10k  [0402]
R27  10k  [0402]
R85  2.2k  [0402]
R96  2.2k  [0402]
TP7  RED  [TP_THVT_100_RND]
TP8  RED  [TP_THVT_100_RND]
U2  TPS79933  [SOT-23_5_63x114_DBV]
U3  SN74CBTLV16210VR  [TVSOP_48_386x177_16]
U4  FT2232HL  [LQFP_64_402x402_20]
U5  93LC46BT-I/SN  [SO_8_193x154_50]
U6  74LVC1G38  [SC70_DCK_G5]
U7  74CBTLV3257  [TSSOP_16_201X177_26]
U8  SN74LVC1G125  [SOT_5_120x69_57]
U10  SN74LVC1G125  [SOT_5_120x69_57]
Y1  12MHz w/ 10pF  [XTAL_4_SM_130x102]

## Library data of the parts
R14 R18 R27 R79 R80 R86 R93 R94 = Res_0402_10k
J12 = CON_SMVT_40X10_SEAF
R1 R2 R11 R95 = Res_0402_4.7k
R12 R13 R15 R20 R21 R25 R85 R96 R97 = Res_0402_2.2K
SW1 = SW_PUSHBUTTON: SILK: SW_RESET
C1 C5-C12 C17 C20 C22-C25 C124-C126 = CAP0603: Mfr_Name: Murata; Mfr_Part_Number: GRM188R71C104KA01D; PART_NUMBER: ECJ-1VB1C104K; TOL: 10%; Voltage: 16V
J3 = HEADER_2x7_100: Mfr_Name: MOLEX; Mfr_Part_Number: 0878321420; TI_SILKTEXT: JTAG
R22-R24 = Res_0402_470
TP9 = TESTPOINT_ORANGE: TI_SILKTEXT: JTAG SEL
U20 = PCA9536DGK
C27 C40 C54 C61 = CAP_1206_47uF: Mfr_Part_Number: GRM31CE70G476ME15L; Voltage: 6.3V
C28 C31 C41 C47 C48 C53 C55 C60 C62 C67 C70-C75 = CAP_0805_4.7uF_X7R_16V: Mfr_Name: MURATA; Mfr_Part_Number: GRM035R60G475ME15D; Voltage: 4V
C29 C32-C37 C39 C42-C45 C49-C52 C56-C59 C63-C66 C68 C76-C83 = CAP_0201_.47uF: Voltage: 4V
C38 C69 = CAP_1206_100uF_6.3V: Mfr_Name: MURATA; Mfr_Part_Number: GRM32ER61A107ME20L; Voltage: 10V
U9 = XC7A100TCSG324
C84-C88 = CAP_0402_0.1uF
C89 C90 = CAP_0402_12pF
D3-D7 = LED: Mfr_Name: OSRAM Opto Semiconductors Inc; Mfr_Part_Number: LB L293-M2P1-36-1-Z; TI_Silktext: MGTAVTT
J5 = SMA-THVT_142-0701-201_REC_0: TI_Silktext: TRIG
J6 = SMA-THVT_142-0701-201_REC_0: TI_Silktext: AC CLK
J7 = SMA-THVT_142-0701-201_REC_0: TI_Silktext: SYNC1
J8 = SMA-THVT_142-0701-201_REC_0: TI_Silktext: SYNC0
R6 R81-R84 = Res_0402_330
R33 R34 = Res_0402_21
R19 R37 = Res_0402_10k_H
R38 = Res_0402_49.9
R39-R42 = Res_0402_100
R43-R46 = Res_0402_18
R7-R9 R87-R91 = RESISTOR: Mfr_Name: Panasonic; Mfr_Part_Number: ERJ-2RKF1002X; Type: Resistor
R92 = Res_0805_Zero_H
R98 R99 = Res_0402_18: Note: DNI
TP11 = TESTPOINT_ORANGE: TI_SILKTEXT: DIG-TP0
TP12 = TESTPOINT_ORANGE: TI_SILKTEXT: DIG-TP1
U18 = SN74LVC07AD: Mfr_Name: Texas Instruments; Mfr_Part_Number: SN74LVC07ADR
Y2 = OSC: 100MHz, 25ppm, CL=15pF, 3.3V, Size=3X5 mm; Mfr_Name: Pletronics; Mfr_Part_Number: SM5545TEV-100.0M; Package: SMD; Terasic_Prt: M0923; Type: Crystal
C91 = CAP_TANT_B_470uF_6.3V
C92 = CAP_0603_0.1uF
C94 C101 C107 = CAP_0603_10uF
C95 C102 C108 = CAP_0603_22uF
C96 C98 C99 C103-C105 C109-C111 C118-C122 = CAP0603: Mfr_Name: Murata; Mfr_Part_Number: GCM188R71C104KA37J; TOL: 10%; Voltage: 16V
C15 C123 = CAP_0603_0.01uF
C127 = CAP_0805_1uF_16V
D2 = LED_GREEN_0: Mfr_Name: Liteon; TI_SILKTEXT: 5V IN
J4 = CONN_JACK_PWR: Mfr_Name: SWITCHCRAFT; Mfr_Part_Number: RAPC722X; Note: DNI
J10 = HEADER_1x3_100: Note: SHUNT 2-3; TI_SILKTEXT: PWR SEL
J13 = HEADER_1x3_100: Note: SHUNT 1-2; TI_SILKTEXT: PWR SEL2
R4 R26 = Res_0402_1k
R49 R50 R56 R62 = Res_0603_10k_H
R51 R57 = Res_0603_24.9: Mfr_Part_Number: ERJ-3EKF2492V
R52 R58 = Res_0603_100k
R53 R54 R59 R60 R65 R66 R71 R72 = Res_0402_1ohm: Mfr_Part_Number: ERJ-3GEYJ100V
R63 = Res_0603_24.9: Mfr_Part_Number: ERJ-3EKF7682V
R64 = Res_0603_100k: Mfr_Part_Number: ERJ-3EKF1243V
R73-R76 = Res_0603_.1: Mfr_Name: YAGEO; Mfr_Part_Number: RL1210FR-070R1L
R77 R78 = Res_0603_Zero_H
TP1-TP3 = TESTPOINT_BLK
TP4 = TESTPOINT_RED: TI_SILKTEXT: 2.5V
TP5 = TESTPOINT_RED: TI_SILKTEXT: 1.8V
TP6 = TESTPOINT_RED: TI_SILKTEXT: 3.3V
TP10 = TESTPOINT_RED: TI_SILKTEXT: 5V_EXT
TP15 = TESTPOINT_RED: TI_SILKTEXT: 5V_PWR
TP16 = TESTPOINT_RED: TI_SILKTEXT: 1V
U1 = TPS73625
U11 U13 U15 = TPS82085
U12 U14 U16 U17 = INA226AIDGSR
Z_SH-H1 Z_SH-H2 = SHUNT-HEADER_-_3POS
MT1-MT4 = MOUNTING_HOLE_1_3_16: Mfr_Part_Number: 2104-440-AL
Z_BOARD1 = BARE_BOARD: Mfr_Name: Gorilla; Mfr_Part_Number: TSW1418 REV E2
Z_SCREW1-Z_SCREW4 = STANDOFF-SCREW_3_8
C2 C14 = CAP_NP_0: Mfr_Name: Kemet; Mfr_Part_Number: C0603C475K8PACTU; TOL: 10%; VOLTAGE: 10V
C3 C13 = CAP_0603_2.2uF
C4 = CAP_0603_3.3uF
C16 = CAP_0402_2.2uF
C18 = CAP_0402_100pF
C19 C21 = CAP_0402_18pF
FB1-FB4 = FERRITE_BEAD_0603_330_H: Mfr_Part_Number: BLM18KG601SH1D
J2 = USB_MINI_AB_MNE20-5G5P10: Mfr_Name: WURTH ELEKTRONIK; Mfr_Part_Number: 651305142821; TI_SILKTEXT: 5V_USB
J11 = HEADER_2x4_100: TI_SILKTEXT: SPI
R3 = R: Mfr_Name: PANASONIC; Mfr_Part_Number: ERJ-3LWFR010V; TOL: 1%; Wattage: 1/10W
R5 = Res_0402_12.1K
R10 = RESISTOR: Mfr_Name: Panasonic; Mfr_Part_Number: ERJ-2RKF2201X; Type: Resistor
TP7 = TESTPOINT_RED: TI_SILKTEXT: 5VUSB
TP8 = TESTPOINT_RED: TI_SILKTEXT: 5V_USB
U2 = TPS79933
U3 = SN74CBTLV16210DGV
U4 = FT2232HL: Mfr_Part_Number: FT2232HL-REEL
U5 = EEPROM: 93LC46B-I/SN,Serial EEPROM, 64 x 16bit, 2.5V-5.5V; Mfr_Name: Microchip; Package: SMD; Terasic_Prt: M0252; Type: Memory
U6 = 74LVC1G38
U7 = SN74CBTLV3257PWR: Mfr_Name: Texas Instruments
U8 U10 = SN74LVC1G125DBVR: Mfr_Name: Texas Instruments
Y1 = CRYSTAL1-4_SM: Mfr_Name: Abracon; Mfr_Part_Number: ABM8G-12.000MHZ-B4Y-T

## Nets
1.8V: C27.1 C28.1 C29.1 C31.1 C32.1 C33.1 C34.1 C35.1 C102.1 C104.1 J13.3 R64.1 TP5.1(TP) U9.F12(VCCAUX) U9.H10(VCCADC_0) U9.H12(VCCAUX) U9.K12(VCCAUX) U9.M12(VCCAUX) U13.8(VOUT)
1.8V_USB: C4.1 C5.1 C6.1 C7.1 U4.12(VCORE) U4.37(VCORE) U4.49(VREGOUT) U4.64(VCORE)
1V: C36.1 C37.1 C38.1 C69.1 C70.1 C71.1 C72.1 C73.1 C74.1 C75.1 C76.1 C77.1 C78.1 C79.1 C80.1 C81.1 C82.1 C83.1 C95.1 C98.1 R51.1 TP16.1(TP) U9.F8(VCCINT) U9.F10(VCCBRAM) U9.G7(VCCINT) U9.G9(VCCINT) U9.G11(VCCBRAM) U9.H8(VCCINT) U9.J7(VCCINT) U9.J11(VCCINT) U9.K8(VCCINT) U9.L7(VCCINT) U9.L11(VCCINT) U9.M8(VCCINT) U9.M10(VCCINT) U9.N7(VCCINT) U9.N9(VCCINT) U9.N11(VCCINT) U11.8(VOUT)
2.5V: C118.1 C122.1 J13.1 TP4.1(TP) U1.5(OUT)
3.3V: C17.1 C25.1 C39.1 C61.1 C62.1 C63.1 C64.1 C65.1 C66.1 C67.1 C68.1 C84.1 C86.2 C88.2 C99.1 C105.1 C108.1 C110.1 C111.1 C120.1 C124.1 C125.1 C126.1 D3.1(ANODE) D4.1(ANODE) D5.1(ANODE) D6.1(ANODE) D7.1(ANODE) J3.2 J12.C39 J12.D32 J12.D36 J12.D38 J12.D40 R12.1 R15.2 R19.2 R20.1 R21.1 R22.1 R24.1 R25.1 R37.1 R39.1 R41.1 R63.1 R79.1 R80.1 R85.2 R86.1 R87.1 R88.1 R89.1 R90.1 R91.1 R93.1 R94.1 R95.1 TP6.1(TP) U3.15(VCC) U7.16(VCC) U8.5(VCC) U9.A17(VCCO_15) U9.B10(VCCO_16) U9.C13(VCCO_15) U9.D16(VCCO_15) U9.G15(VCCO_15) U9.H18(VCCO_15) U9.K14(VCCO_15) U9.R9(VCCO_0) U10.5(VCC) U12.6(VS) U14.2(A0) U14.6(VS) U15.8(VOUT) U16.6(VS) U17.6(VS) U18.13(6A) U18.14(VCC) U20.8(VCC) Y2.4(VCC)
3.3V_USB: C3.1 C8.1 C9.1 C10.1 C11.1 C20.1 C24.1 FB1.2 FB2.2 R1.1 R2.1 R4.1 R7.1 R8.1 R9.1 R13.1 R27.1 R96.1 R97.1 U2.5(OUT) U4.20(VCCIO) U4.31(VCCIO) U4.42(VCCIO) U4.50(VREGIN) U4.56(VCCIO) U5.8(VCC) U6.5(VCC)
5V_EXT: J4.1 J10.1 TP10.1(TP)
5V_PWR: C91.1 J10.2 R26.1 R50.2 R53.1 R56.2 R59.1 R62.2 R65.1 R71.1 R73.1 R74.1 R75.1 R76.1 TP15.1(TP)
5V_USB: C13.1 J10.3 R3.2 R11.1 TP8.1(TP) U2.1(IN) U2.3(EN)
GND: C1.2 C2.2 C3.2 C4.2 C5.2 C6.2 C7.2 C8.2 C9.2 C10.2 C11.2 C12.2 C13.2 C14.2 C15.2 C16.2 C17.2 C18.2 C19.2 C20.2 C21.2 C22.2 C23.2 C24.2 C25.2 C27.2 C28.2 C29.2 C31.2 C32.2 C33.2 C34.2 C35.2 C36.2 C37.2 C38.2 C39.2 C40.2 C41.2 C42.2 C43.2 C44.2 C45.2 C47.2 C48.2 C49.2 C50.2 C51.2 C52.2 C53.2 C54.2 C55.2 C56.2 C57.2 C58.2 C59.2 C60.2 C61.2 C62.2 C63.2 C64.2 C65.2 C66.2 C67.2 C68.2 C69.2 C70.2 C71.2 C72.2 C73.2 C74.2 C75.2 C76.2 C77.2 C78.2 C79.2 C80.2 C81.2 C82.2 C83.2 C84.2 C86.1 C88.1 C89.2 C90.2 C91.2 C92.2 C94.2 C95.2 C98.2 C99.2 C101.2 C102.2 C104.2 C105.2 C107.2 C108.2 C110.2 C111.2 C118.2 C120.2 C121.2 C122.2 C123.2 C124.2 C125.2 C126.2 C127.2 D2.2(CATHODE) FB4.2 J2.5(GND) J3.1 J3.3 J3.5 J3.7 J3.9 J3.11 J3.13 J4.2 J4.3 J5.2(GND) J5.3(GND) J5.4(GND) J5.5(GND) J6.2(GND) J6.3(GND) J6.4(GND) J6.5(GND) J7.2(GND) J7.3(GND) J7.4(GND) J7.5(GND) J8.2(GND) J8.3(GND) J8.4(GND) J8.5(GND) J11.2 J11.4 J11.6 J11.8 J12.A1 J12.A4 J12.A5 J12.A8 J12.A9 J12.A12 J12.A13 J12.A16 J12.A17 J12.A20 J12.A21 J12.A24 J12.A25 J12.A28 J12.A29 J12.A32 J12.A33 J12.A36 J12.A37 J12.A40 J12.B2 J12.B3 J12.B6 J12.B7 J12.B10 J12.B11 J12.B14 J12.B15 J12.B18 J12.B19 J12.B22 J12.B23 J12.B26 J12.B27 J12.B30 J12.B31 J12.B34 J12.B35 J12.B38 J12.B39 J12.C1 J12.C4 J12.C5 J12.C8 J12.C9 J12.C12 J12.C13 J12.C16 J12.C17 J12.C20 J12.C21 J12.C24 J12.C25 J12.C28 J12.C29 J12.C32 J12.C33 J12.C34 J12.C36 J12.C38 J12.C40 J12.D2 J12.D3 J12.D6 J12.D7 J12.D10 J12.D13 J12.D16 J12.D19 J12.D22 J12.D25 J12.D28 J12.D35 J12.D37 J12.D39 J12.E1 J12.E4 J12.E5 J12.E8 J12.E11 J12.E14 J12.E17 J12.E20 J12.E23 J12.E26 J12.E29 J12.E32 J12.E35 J12.E38 J12.E40 J12.F2 J12.F3 J12.F6 J12.F9 J12.F12 J12.F15 J12.F18 J12.F21 J12.F24 J12.F27 J12.F30 J12.F33 J12.F36 J12.F39 J12.G1 J12.G4 J12.G5 J12.G8 J12.G11 J12.G14 J12.G17 J12.G20 J12.G23 J12.G26 J12.G29 J12.G32 J12.G35 J12.G38 J12.G40 J12.H3 J12.H6 J12.H9 J12.H12 J12.H15 J12.H18 J12.H21 J12.H24 J12.H27 J12.H30 J12.H33 J12.H36 J12.H39 J12.J1 J12.J4 J12.J5 J12.J8 J12.J11 J12.J14 J12.J17 J12.J20 J12.J23 J12.J26 J12.J29 J12.J32 J12.J35 J12.J38 J12.J40 J12.K2 J12.K3 J12.K6 J12.K9 J12.K12 J12.K15 J12.K18 J12.K21 J12.K24 J12.K27 J12.K30 J12.K33 J12.K36 J12.K39 R5.1 R14.2 R18.2 R23.1 R40.2 R42.2 R52.2 R57.2 R58.2 SW1.1 TP1.1(TP) TP2.1(TP) TP3.1(TP) U1.2(GND) U2.2(GND) U3.4(1A3) U3.5(1A4) U3.6(1A5) U3.7(1A6) U3.8(GND1) U3.17(GND2) U3.32(GND3) U3.41(GND4) U4.1(GND) U4.5(GND) U4.10(AGND) U4.11(GND) U4.13(TEST) U4.15(GND) U4.25(GND) U4.35(GND) U4.47(GND) U4.51(GND) U5.5(GND) U6.3(GND) U7.8(GND) U8.2(A) U8.3(GND) U9.A2(GND) U9.A12(GND) U9.B5(GND) U9.B15(GND) U9.C8(GND) U9.C18(GND) U9.D1(GND) U9.D11(GND) U9.E4(GND) U9.E8(VCCBATT_0) U9.E14(GND) U9.F7(GND) U9.F9(GND) U9.F11(GND) U9.F17(GND) U9.G8(GND) U9.G10(GND) U9.G12(GND) U9.H3(GND) U9.H7(GND) U9.H9(GNDADC) U9.H11(GND) U9.H13(GND) U9.J6(GND) U9.J8(GND) U9.J9(VREFN_0) U9.J12(GND) U9.J16(GND) U9.K7(GND) U9.K10(VREFP_0) U9.K11(GND) U9.L2(GND) U9.L8(GND) U9.L9(DXN_0) U9.L10(DXP_0) U9.L12(GND) U9.M5(GND) U9.M7(GND) U9.M9(GND) U9.M11(GND) U9.M15(GND) U9.N8(GND) U9.N10(GND) U9.N12(GND) U9.N18(GND) U9.P1(GND) U9.R4(GND) U9.R14(GND) U9.T7(GND) U9.T17(GND) U9.U10(GND) U9.V3(GND) U9.V13(GND) U10.3(GND) U11.5(GND) U11.6(GND) U11.9(PWRPAD) U12.2(A0) U12.7(GND) U13.5(GND) U13.6(GND) U13.9(PWRPAD) U14.7(GND) U15.5(GND) U15.6(GND) U15.9(PWRPAD) U16.7(GND) U17.7(GND) U18.7(GND) U20.4(GND) Y1.2 Y1.4 Y2.2(GND)
1P0V_SHUNTN: C94.1 R49.1 R54.1 R76.2 U11.3(VIN) U11.4(VIN)
1P8V_SHUNTN: C101.1 R60.1 R74.2 U13.3(VIN) U13.4(VIN)
2P5V_REG_EN: R56.1 R78.2 U1.3(EN) U15.1(EN)
2P5V_SHUNTN: C121.1 R72.1 R75.2 U1.1(IN)
3P3V_SHUNTN: C107.1 R66.1 R73.2 U15.3(VIN) U15.4(VIN)
AC-CLK-IN: C87.1 J6.1(CENTER)
AC_CLK: C87.2 R41.2 R42.1 U9.B8(IO_L12P_T1_MRCC)
ALIVE: R91.2 U9.D12(IO_L6P_T0) U18.11(5A)
BB_RDSTBN: U3.2(1A1) U4.53(BCBUS2)
BB_WRSTBN: U3.3(1A2) U4.52(BCBUS1)
BS_ENA: R27.2 R92.1 U3.47(2~{OE}\) U3.48(1~{OE}\) U6.4(Y)
D0_TCK_SCLK: U4.38(BDBUS0) U7.12(4A)
D1_TDI_MOSI: U4.39(BDBUS1) U7.9(3A)
D2_TDO_MISO: U4.40(BDBUS2) U7.7(2A)
D3_TMS_SEN: U4.41(BDBUS3) U7.4(1A)
DCLK_N: J12.F5 U9.D3(IO_L12N_T1_MRCC_35)
DCLK_P: J12.F4 U9.E3(IO_L12P_T1_MRCC_35)
DCLKIN_FPGA_N: J12.K17 U9.F3(IO_L13N_T2_MRCC_35)
DCLKIN_FPGA_P: J12.K16 U9.F4(IO_L13P_T2_MRCC_35)
DM: J2.2(D-) U4.7(DM)
DONE_0: R20.2 U9.P10(DONE_0) U20.3(P2)
DP: J2.3(D+) U4.8(DP)
EEDATA: R10.1 U4.61(EEDATA) U5.3(DI)
FCLK_N: J12.E3 U9.D4(IO_L11N_T1_SRCC_35)
FCLK_P: J12.E2 U9.D5(IO_L11P_T1_SRCC_35)
FIFO_CLKOUT: U3.10(1A8) U4.32(ACBUS5)
FIFO_D0: U3.24(2A10) U4.16(ADBUS0)
FIFO_D1: U3.23(2A9) U4.17(ADBUS1)
FIFO_D2: U3.22(2A8) U4.18(ADBUS2)
FIFO_D3: U3.21(2A7) U4.19(ADBUS3)
FIFO_D4: U3.20(2A6) U4.21(ADBUS4)
FIFO_D5: U3.19(2A5) U4.22(ADBUS5)
FIFO_D6: U3.18(2A4) U4.23(ADBUS6)
FIFO_D7: U3.16(2A3) U4.24(ADBUS7)
FIFO_OEN: U3.9(1A7) U4.33(ACBUS6)
FIFO_RDN: U3.12(1A10) U4.28(ACBUS2)
FIFO_RXFN: U3.14(2A2) U4.26(ACBUS0)
FIFO_TXEN: U3.13(2A1) U4.27(ACBUS1)
FIFO_WRN: U3.11(1A9) U4.29(ACBUS3)
FMC_GPIO_0: J12.G21 U9.L18(IO_L4P_T0_D04)
FMC_GPIO_1: J12.G22 U9.M18(IO_L4N_T0_D05)
FMC_GPIO_2: J12.G24 U9.R12(IO_L5P_T0_D06)
FMC_GPIO_3: J12.G25 U9.R13(IO_L5N_T0_D07)
FMC_MISO: J12.G30 U9.N14(IO_L8P_T1_D11)
FMC_MOSI: J12.G31 U9.T18(IO_L7N_T1_D10)
FMC_MOSI_EN: J12.G33 U9.R18(IO_L7P_T1_D09)
FMC_SCL: J12.G34 U9.P14(IO_L8N_T1_D12)
FMC_SCLK: J12.G27 U9.L13(IO_L6P_T0_FCS_B)
FMC_SDA_IN: J12.G37 U9.P18(IO_L9N_T1_DQS_D13)
FMC_SDA_OUT: J12.G36 U9.N17(IO_L9P_T1_DQS)
FMC_SEN: J12.G28 U9.M13(IO_L6N_T0_D08_VREF)
FPGA-TP0: R33.1 U9.M2(IO_L4N_T0_34)
FPGA-TP1: R34.1 U9.M3(IO_L4P_T0_34)
FPGA_CLK_N: J12.H5 U9.P5(IO_L13N_T2_MRCC_34)
FPGA_CLK_P: J12.H4 U9.N5(IO_L13P_T2_MRCC_34)
FPGA_REFCLK_N: J12.G7 U9.T4(IO_L12N_T1_MRCC_34)
FPGA_REFCLK_P: J12.G6 U9.T5(IO_L12P_T1_MRCC_34)
FTDI-BB-RDSTBN: U3.46(1B1) U9.J17(IO_L23P_T3_FOE_B)
FTDI-BB-WRSTBN: U3.45(1B2) U9.J18(IO_L23N_T3_FWE_B)
FTDI-FIFO-CLKOUT: U3.38(1B8) U9.D15(IO_L12P_T1_MRCC)
FTDI-FIFO-D0: U3.25(2B10) U9.A13(IO_L9P_T1_DQS_AD3P)
FTDI-FIFO-D1: U3.26(2B9) U9.B13(IO_L2P_T0_AD8P)
FTDI-FIFO-D2: U3.27(2B8) U9.A14(IO_L9N_T1_DQS_AD3N)
FTDI-FIFO-D3: U3.28(2B7) U9.B14(IO_L2N_T0_AD8N)
FTDI-FIFO-D4: U3.29(2B6) U9.A15(IO_L8P_T1_AD10P)
FTDI-FIFO-D5: U3.30(2B5) U9.C14(IO_L1N_T0_AD0N)
FTDI-FIFO-D6: U3.31(2B4) U9.A16(IO_L8N_T1_AD10N)
FTDI-FIFO-D7: U3.33(2B3) U9.B16(IO_L7P_T1_AD2P)
FTDI-FIFO-OEN: U3.39(1B7) U9.D17(IO_L16N_T2_A27)
FTDI-FIFO-RDN: U3.36(1B10) U9.B18(IO_L10P_T1_AD11P)
FTDI-FIFO-RXFN: U3.34(2B2) U9.A18(IO_L10N_T1_AD11N)
FTDI-FIFO-TXEN: U3.35(2B1) U9.B17(IO_L7N_T1_AD2N)
FTDI-FIFO-WRN: U3.37(1B9) U9.C17(IO_L20N_T3_A19)
HA02_N: J12.K8 U9.C7(IO_L4N_T0_35)
HA02_P: J12.K7 U9.D8(IO_L4P_T0_35)
HA03_N: J12.J7 U9.D7(IO_L6N_T0_VREF_35)
HA03_P: J12.J6 U9.E7(IO_L6P_T0_35)
HA04_N: J12.F8 U9.B1(IO_L9P_T1_DQS_AD7P_35)
HA04_P: J12.F7 U9.A1(IO_L9N_T1_DQS_AD7N_35)
HA05_N: J12.E7 U9.A3(IO_L8N_T1_AD14N_35)
HA05_P: J12.E6 U9.A4(IO_L8P_T1_AD14P_35)
HA06_N: J12.K11 U9.B6(IO_L2N_T0_AD12N_35)
HA06_P: J12.K10 U9.B7(IO_L2P_T0_AD12P_35)
HA07_N: J12.J10 U9.E1(IO_L18N_T2_35)
HA07_P: J12.J9 U9.F1(IO_L18P_T2_35)
HA08_N: J12.F11 U9.E6(IO_L5P_T0_AD13P_35)
HA08_P: J12.F10 U9.E5(IO_L5N_T0_AD13N_35)
HA09_N: J12.E10 U9.A5(IO_L3N_T0_DQS_AD5N_35)
HA09_P: J12.E9 U9.A6(IO_L3P_T0_DQS_AD5P_35)
HA10_N: J12.K14 U9.C1(IO_L16N_T2_35)
HA10_P: J12.K13 U9.C2(IO_L16P_T2_35)
HA11_N: J12.J13 U9.B4(IO_L7N_T1_AD6N_35)
HA11_P: J12.J12 U9.C4(IO_L7P_T1_AD6P_35)
HA12_N: J12.F14 U9.H1(IO_L17P_T2_35)
HA12_P: J12.F13 U9.G1(IO_L17N_T2_35)
HA13_N: J12.E13 U9.B2(IO_L10N_T1_AD15N_35)
HA13_P: J12.E12 U9.B3(IO_L10P_T1_AD15P_35)
HA14_N: J12.J16 U9.C6(IO_L1P_T0_AD4P_35)
HA14_P: J12.J15 U9.C5(IO_L1N_T0_AD4N_35)
HA15_N: J12.F17 U9.J3(IO_L22P_T3_35)
HA15_P: J12.F16 U9.J2(IO_L22N_T3_35)
HA16_N: J12.E16 U9.E2(IO_L14P_T2_SRCC_35)
HA16_P: J12.E15 U9.D2(IO_L14N_T2_SRCC_35)
HA18_N: J12.J19 U9.H6(IO_L24P_T3_35)
HA18_P: J12.J18 U9.H5(IO_L24N_T3_35)
HA19_N: J12.F20 U9.K2(IO_L23P_T3_35)
HA19_P: J12.F19 U9.K1(IO_L23N_T3_35)
HA20_N: J12.E19 U9.H4(IO_L21N_T3_DQS_35)
HA20_P: J12.E18 U9.J4(IO_L21P_T3_DQS_35)
HA21_N: J12.K20 U9.H2(IO_L15P_T2_DQS_35)
HA21_P: J12.K19 U9.G2(IO_L15N_T2_DQS_35)
HA22_N: J12.J22 U9.G4(IO_L20P_T3_35)
HA22_P: J12.J21 U9.G3(IO_L20N_T3_35)
HA23_N: J12.K23 U9.G6(IO_L19P_T3_35)
HA23_P: J12.K22 U9.F6(IO_L19N_T3_VREF_35)
INIT_B_0: R21.2 U9.P7(INIT_B_0) U20.2(P1)
JTAG_BS_EN: R19.1 R92.2 U7.15(~{OE})
JTAG_SEL: R18.1 TP9.1(TP) U7.1(S) U20.5(P3)
LED0: R88.2 U9.B12(IO_L3N_T0_DQS_AD1N) U18.1(1A)
LED1: R87.2 U9.B11(IO_L4P_T0) U18.3(2A)
LED2: R89.2 U9.F15(IO_L14P_T2_SRCC) U18.5(3A)
LED3: R90.2 U9.H14(IO_L15P_T2_DQS) U18.9(4A)
MISO: J11.3 U7.6(2B2) U9.J14(IO_L19P_T3_A22)
MOSI: U7.10(3B2) U9.G17(IO_L18N_T2_A23) U10.2(A)
MOSI_Z: J11.5 U10.4(Y)
OSC-OUT: R38.2 U9.H16(IO_L13P_T2_MRCC)
PROGRAM_B_0: R86.2 U9.P9(PROGRAM_B_0) U20.1(P0)
SCL: R97.2 U4.44(BDBUS5) U9.F18(IO_L22N_T3_A16) U12.1(A1) U12.5(SCL) U14.1(A1) U14.5(SCL) U16.1(A1) U16.5(SCL) U17.1(A1) U17.2(A0) U17.5(SCL) U20.6(SCL)
SCLK: J11.7 U7.13(4B2) U9.J13(IO_L17N_T2_A25)
SDA: R85.1 U4.46(BDBUS7) U8.4(Y) U9.G18(IO_L22P_T3_A17) U12.4(SDA) U14.4(SDA) U16.2(A0) U16.4(SDA) U17.4(SDA) U20.7(SDA)
SDA_OUT: R96.2 U4.45(BDBUS6) U8.1(~{OE})
SEN: J11.1 U7.3(1B2) U9.H17(IO_L18P_T2_A24)
SOUT0: C90.1 R45.1 R46.2 R99.2
SOUT1: C89.1 R43.1 R44.2 R98.2
SPI_D_Z: U4.43(BDBUS4) U9.J15(IO_L24N_T3_RS0) U10.1(~{OE})
SYNC0: R46.1 U9.A10(IO_L14P_T1_SRCC)
SYNC0_VADJ: R99.1 U9.R3(IO_L11P_T1_SRCC_34)
SYNC1: R44.1 U9.A11(IO_L4N_T0)
SYNC1_VADJ: R98.1 U9.P4(IO_L14P_T2_SRCC_34)
SYNC-OUT-0: J8.1(CENTER) R45.2
SYNC-OUT-1: J7.1(CENTER) R43.2
TCK: J3.6 R79.2 U7.14(4B1) U9.E10(TCK_0)
TDI: J3.10 U7.11(3B1) U9.E11(TDI_0)
TDO: J3.8 U7.5(2B1) U9.E13(TDO_0)
TMS: J3.4 R80.2 U7.2(1B1) U9.E12(TMS_0)
TRIG: C85.2 R39.2 R40.1 U9.A9(IO_L14N_T1_SRCC)
TRIG-IN: C85.1 J5.1(CENTER)
USB_EECLK: R8.2 U4.62(EECLK) U5.2(CLK)
USB_EECS: R7.2 U4.63(EECS) U5.1(CS)
USB_REF: R5.2 U4.6(REF)
USB_RST: C18.1 R4.2 U4.14(\\~{RESET})
VADJ: C40.1 C41.1 C42.1 C43.1 C44.1 C45.1 C47.1 C48.1 C49.1 C50.1 C51.1 C52.1 C53.1 C54.1 C55.1 C56.1 C57.1 C58.1 C59.1 C60.1 C127.1 J12.E39 J12.F40 J12.G39 J12.H40 J13.2 U9.A7(VCCO_35) U9.C3(VCCO_35) U9.D6(VCCO_35) U9.F2(VCCO_35) U9.G5(VCCO_35) U9.J1(VCCO_35) U9.K4(VCCO_34) U9.L15(IO_L3P_T0_DQS_PUDC_B) U9.L17(VCCO_14) U9.N3(VCCO_34) U9.N13(VCCO_14) U9.P6(VCCO_34) U9.P16(VCCO_14) U9.T2(VCCO_34) U9.T12(VCCO_14) U9.U5(VCCO_34) U9.U15(VCCO_14) U9.V8(VCCO_34) U9.V18(VCCO_14)
N24747082: R9.2 R10.2 U5.4(DO)
N25673570: C1.1 C2.1 FB1.1 U4.9(VPLL)
N25674940: C12.1 C14.1 FB2.1 U4.4(VPHY)
N27319544: C19.1 U4.2(OSCI) Y1.1
N27322325: C21.1 U4.3(OSCO) Y1.3
N29832220: FB4.1 J2.6(GND1) J2.7(GND2) J2.8(GND3) J2.9(GND4)
N46253696: C16.1 FB3.1 J2.1(VBUS)
N46253708: FB3.2 R3.1 TP7.1(TP)
N46266315: C15.1 U2.4(NR/FB)
N46266800: R11.2 R14.1 U4.59(BCBUS7)
N46270507: R22.2 U9.P11(M2_0)
N46270525: R23.2 U9.P13(M1_0)
N46270552: R24.2 U9.P12(M0_0)
N46270638: R25.2 U9.P8(CFGBVS_0)
N46271778: R1.2 U4.30(ACBUS4)
N46271783: R2.2 U4.55(BCBUS4)
N46280543: C23.1 R13.2 U6.2(B)
N46280553: C22.1 R12.2 U6.1(A)
N46323629: R33.2 TP11.1(TP)
N46323688: R34.2 TP12.1(TP)
N46333997: C92.1 R49.2 U11.1(EN)
N46334199: R50.1 R77.2 U13.1(EN)
N46334233: R51.2 R52.1 U11.7(FB)
N46334693: C96.2 R54.2 U12.8(VBUS) U12.9(VIN-)
N46334712: C96.1 R53.2 U12.10(VIN+)
N46335690: R58.1 R64.2 U13.7(FB)
N46335801: C103.2 R60.2 U14.8(VBUS) U14.9(VIN-)
N46335828: C103.1 R59.2 U14.10(VIN+)
N46336358: R62.1 U15.2(PG)
N46336380: R57.1 R63.2 U15.7(FB)
N46336491: C109.2 R66.2 U16.8(VBUS) U16.9(VIN-)
N46336518: C109.1 R65.2 U16.10(VIN+)
N46342790: C119.2 R72.2 U17.8(VBUS) U17.9(VIN-)
N46342817: C119.1 R71.2 U17.10(VIN+)
N46365358: C123.1 U1.4(NR)
N46372732: R37.2 Y2.1(EN)
N46372902: R38.1 Y2.3(OUT)
N46384300: D3.2(CATHODE) R81.1
N46384467: D4.2(CATHODE) R6.1
N46384557: D5.2(CATHODE) R82.1
N46384754: D6.2(CATHODE) R83.1
N46384902: D7.2(CATHODE) R84.1
N46387156: D2.1(ANODE) R26.2
N46388372: R6.2 U18.2(1Y)
N46388377: R81.2 U18.4(2Y)
N46388382: R82.2 U18.6(3Y)
N46388387: R83.2 U18.8(4Y)
N46388402: R84.2 U18.10(5Y)
N46435188: R15.1 SW1.2 U9.C10(IO_L13N_T1_MRCC)
N46505112: J12.F1 R93.2
N46505156: J12.D1 R94.2
N46505187: J12.H1 R95.2
N46516385: R77.1 U11.2(PG)
N46516391: R78.1 U13.2(PG)

Not connected (* = marked no-connect by the designer): J2 4(ID)*; J3 12* 14*; J12 A2 A3 A6 A7 A10 A11 A14 A15 A18 A19 A22 A23 A26 A27 A30 A31 A34 A35 A38 A39 B1 B4 B5 B8 B9 B12 B13 B16 B17 B20 B21 B24 B25 B28 B29 B32 B33 B36 B37 B40 C2 C3 C6 C7 C10 C11 C14 C15 C18 C19 C22 C23 C26 C27 C30 C31 C35 C37 D4 D5 D8 D9 D11 D12 D14 D15 D17 D18 D20 D21 D23 D24 D26 D27 D29 D30 D31 D33 D34 E21 E22 E24 E25 E27 E28 E30 E31 E33 E34 E36 E37 F22 F23 F25 F26 F28 F29 F31 F32 F34 F35 F37 F38 G2 G3 G9 G10 G12 G13 G15 G16 G18 G19 H2 H7 H8 H10 H11 H13 H14 H16 H17 H19 H20 H22 H23 H25 H26 H28 H29 H31 H32 H34 H35 H37 H38 J2 J3 J24 J25 J27 J28 J30 J31 J33 J34 J36 J37 J39 K1 K4 K5 K25 K26 K28 K29 K31 K32 K34 K35 K37 K38 K40; MT1 1; MT2 1; MT3 1; MT4 1; U3 1(NC)* 40(1B6)* 42(1B5)* 43(1B4)* 44(1B3)*; U4 34(ACBUS7)* 36(SUSPEND)* 48(BCBUS0)* 54(BCBUS3)* 57(BCBUS5)* 58(BCBUS6)* 60(PWREN)*; U5 6(NC2)* 7(NC1)*; U9 A8(IO_L12N_T1_MRCC) B9(IO_L11N_T1_SRCC) C9(IO_L11P_T1_SRCC) C11(IO_L13P_T1_MRCC) C12(IO_L3P_T0_DQS_AD1P) C15(IO_L12N_T1_MRCC) C16(IO_L20P_T3_A20) D9(IO_L6N_T0_VREF) D10(IO_L19N_T3_VREF) D13(IO_L6N_T0_VREF) D14(IO_L1P_T0_AD0P) D18(IO_L21N_T3_DQS_A18) E9(CCLK_0)* E15(IO_L11P_T1_SRCC) E16(IO_L11N_T1_SRCC) E17(IO_L16P_T2_A28) E18(IO_L21P_T3_DQS) F5(IO_0_35) F13(IO_L5P_T0_AD9P) F14(IO_L5N_T0_AD9N) F16(IO_L14N_T2_SRCC) G13(IO_0_15) G14(IO_L15N_T2_DQS_ADV_B) G16(IO_L13N_T2_MRCC) H15(IO_L19N_T3_A21_VREF) J5(IO_25_35) J10(VP_0)* K3(IO_L2P_T0_34) K5(IO_L5P_T0_34) K6(IO_0_34) K9(VN_0)* K13(IO_L17P_T2_A26) K15(IO_L24P_T3_RS1) K16(IO_25_15) K17(IO_L1P_T0_D00_MOSI) K18(IO_L1N_T0_D01_DIN) L1(IO_L1P_T0_34) L3(IO_L2N_T0_34) L4(IO_L5N_T0_34) L5(IO_L6N_T0_VREF_34) L6(IO_L6P_T0_34) L14(IO_L2P_T0_D02) L16(IO_L3N_T0_DQS_EMCCLK) M1(IO_L1N_T0_34) M4(IO_L16P_T2_34) M6(IO_L18P_T2_34) M14(IO_L2N_T0_D03) M16(IO_L10P_T1_D14) M17(IO_L10N_T1_D15) N1(IO_L3N_T0_DQS_34) N2(IO_L3P_T0_DQS_34) N4(IO_L16N_T2_34) N6(IO_L18N_T2_34) N15(IO_L11P_T1_SRCC) N16(IO_L11N_T1_SRCC) P2(IO_L15P_T2_DQS_34) P3(IO_L14N_T2_SRCC_34) P15(IO_L13P_T2_MRCC) P17(IO_L12P_T1_MRCC) R1(IO_L17P_T2_34) R2(IO_L15N_T2_DQS_34) R5(IO_L19N_T3_VREF_34) R6(IO_L19P_T3_34) R7(IO_L23P_T3_34) R8(IO_L24P_T3_34) R10(IO_25_14) R11(IO_0_14) R15(IO_L13N_T2_MRCC) R16(IO_L15P_T2_DQS_RDWR_B) R17(IO_L12N_T1_MRCC) T1(IO_L17N_T2_34) T3(IO_L11N_T1_SRCC_34) T6(IO_L23N_T3_34) T8(IO_L24N_T3_34) T9(IO_L24P_T3_A01_D17) T10(IO_L24N_T3_A00_D16) T11(IO_L19P_T3_A10_D26) T13(IO_L23P_T3_A03_D19) T14(IO_L14P_T2_SRCC) T15(IO_L14N_T2_SRCC) T16(IO_L15N_T2_DQS_DOUT_CSO_B) U1(IO_L7P_T1_34) U2(IO_L9P_T1_DQS_34) U3(IO_L8N_T1_34) U4(IO_L8P_T1_34) U6(IO_L22N_T3_34) U7(IO_L22P_T3_34) U8(IO_25_34) U9(IO_L21P_T3_DQS_34) U11(IO_L19N_T3_A09_D25_VREF) U12(IO_L20P_T3_A08_D24) U13(IO_L23N_T3_A02_D18) U14(IO_L22P_T3_A05_D21) U16(IO_L18P_T2_A12_D28) U17(IO_L17P_T2_A14_D30) U18(IO_L17N_T2_A13_D29) V1(IO_L7N_T1_34) V2(IO_L9N_T1_DQS_34) V4(IO_L10N_T1_34) V5(IO_L10P_T1_34) V6(IO_L20N_T3_34) V7(IO_L20P_T3_34) V9(IO_L21N_T3_DQS_34) V10(IO_L21P_T3_DQS) V11(IO_L21N_T3_DQS_A06_D22) V12(IO_L20N_T3_A07_D23) V14(IO_L22N_T3_A04_D20) V15(IO_L16P_T2_CSI_B) V16(IO_L16N_T2_A15_D31) V17(IO_L18N_T2_A11_D27); U12 3(ALERT)*; U14 3(ALERT)*; U16 3(ALERT)*; U17 3(ALERT)*; U18 12(6Y)*

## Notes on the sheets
sheet 1
- Drawn:
- JV SMITH   02/2018
- Engineer:
- B. KINCAID   02/2018
sheet 2
- CLOSED = USE FTDI
- OPEN = USE EXT JTAG
sheet 3
- ADC Interface
- POWER GOOD MONITOR
- 3.3V available on FMC
- VADJ available on FMC
- Mates to male bottom side FMC on the ADC35* EVMs.
- All routed I/O is based on VADJ
- 12V not available on FMC
sheet 4
- ADC Interface
- Mates to male bottom side FMC on the ADC35* EVMs.
sheet 5
- USB
- NAND BS_ENA GOES LOW
- WHEN POWER GOOD.
- JTAG and SPI are muxed from FTDI
- I2C configurations
- SCL drive only
- SDA_OUT H/L         SDA Z/L
- ADD NET NAMES IN SILKSCREEN
- SDA readback
- SEN drive
- SPI configurations
- SCLK drive
- MISO read
- used to high Z MOSI
- MOSI  ---- MOSI_Z drive or Z
- for 3 wire SPI
- SPI_D_Z -- MOSI_Z drive or Z
sheet 6
- FPGA JTAG CONFIG
- CFGBVS= 1(VCC_0=3.3V)
- M[2:0]= 101
- TCK, TMS, TDI, TDO = from FTDI device through MUX
- PROGRAM_B=I2C expander P0, write, pulse low to enable configuration mode
- INIT_B= I2C expander P1, read only
- DONE= I2C expander P2, read only
- CCLK= no connect
- PUDC_B= 3.3V
- PCA9536 address 0x82
- - All pins input at power up
- - Configure 0x03 F6 (wrrw) at startup
- - Read 0x00 [JTAG_SEL  DONE  INIT_B  PROGRAM_B]
- - Write 0X01 [JTAG_SEL   X    X      PROGRAM_B]
- address 0x82
sheet 7
- VCC = VADJ
- These signals are
- wired through FPGA
- to FMC
- VCC = 3.3V
sheet 8
- VCC = VADJ
- VCC = 3.3V
- VCC = VADJ
sheet 9
- 5V DC
  INPUT
- 2.5V VADJ, LVDS
- EXT
- 1.8V VADJ, CMOS
- USB
- 0x9B
- 0x9A
- 0x9C
- 0x9E
sheet 10
- VCCAUX
- VCC0_14
- VCCBRAM
- VCC0_15
- VCC0_34
- VCCO_0
- VCCO_16
- VCC0_35
- VCCINT
sheet 11
- MECHANICAL PARTS
